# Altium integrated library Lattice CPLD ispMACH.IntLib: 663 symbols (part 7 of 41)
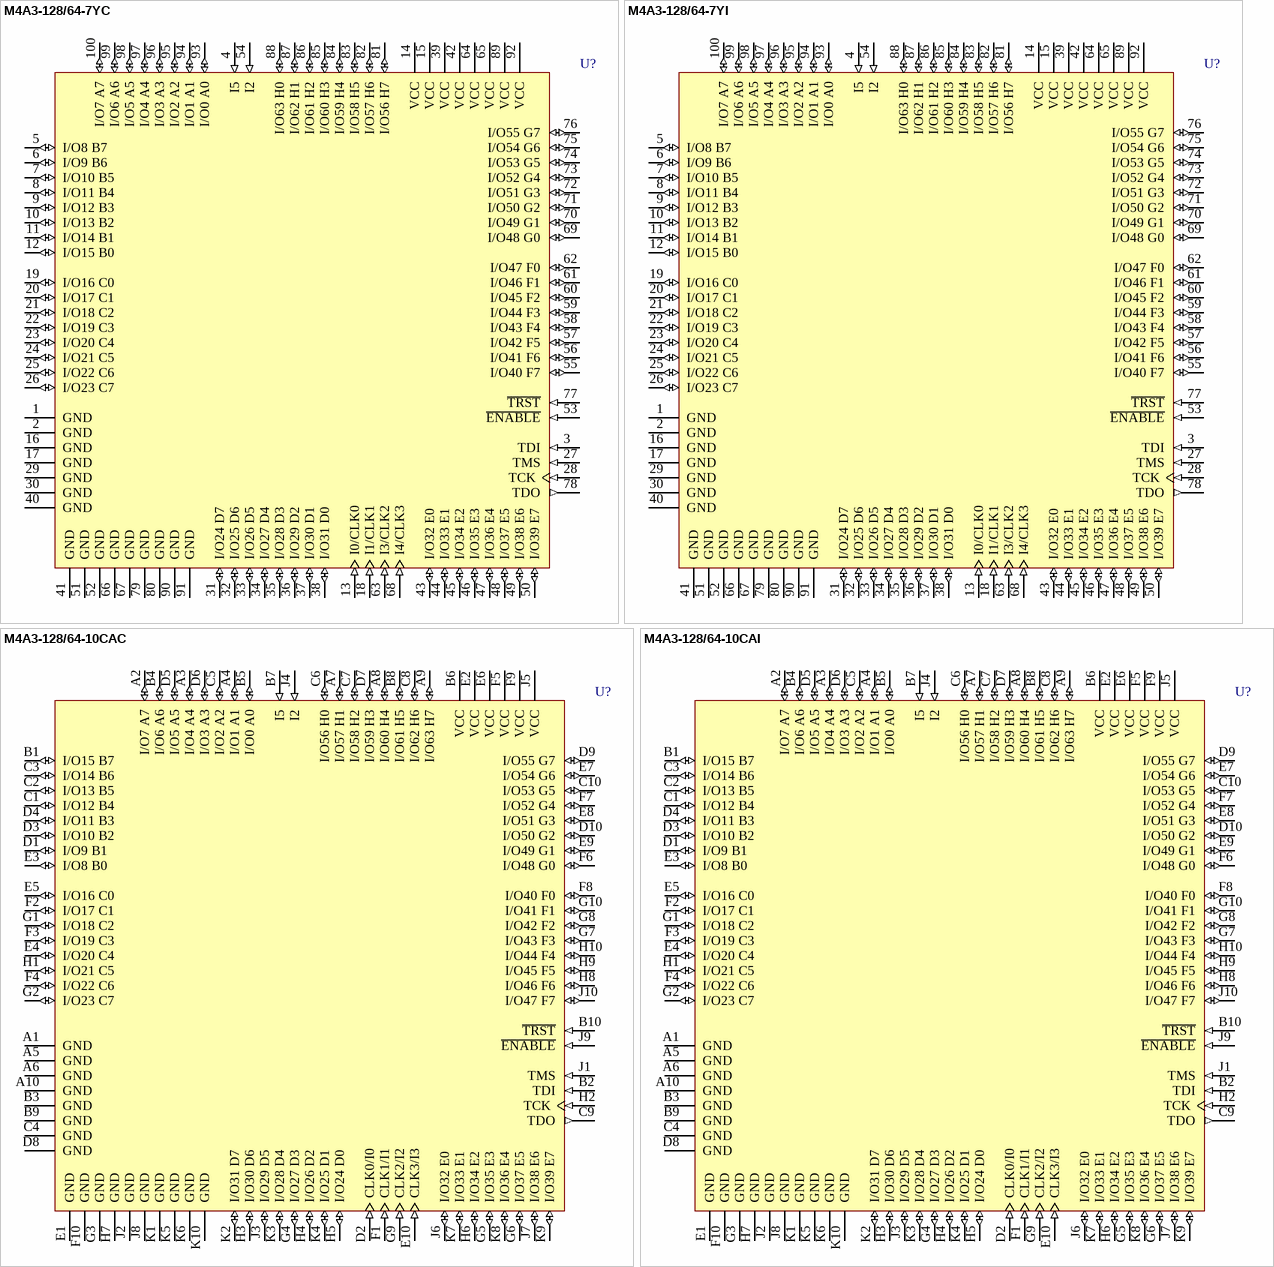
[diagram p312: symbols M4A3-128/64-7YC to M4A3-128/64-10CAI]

## M4A3-128/64-7YI
designator U?
High-Performance EE CMOS In-System Programmable Logic
footprint PQFP100_N (QFP, 100-Leads, Body 20x14mm, Pitch 0.65mm, IPC Medium Density)
footprint PQFP100_L (QFP, 100-Leads, Body 20x14mm, Pitch 0.65mm, IPC High Density)
footprint PQFP100_M (QFP, 100-Leads, Body 20x14mm, Pitch 0.65mm, IPC Low Density)
3D model PQFP-100 (100-Pin Quad Flat Pack Rectangular 0.65 mm Pitch)
pins: 1 GND (power), 2 GND (power), 3 TDI (in), 4 I5 (in), 5 I/O8 B7 (io), 6 I/O9 B6 (io), 7 I/O10 B5 (io), 8 I/O11 B4 (io), 9 I/O12 B3 (io), 10 I/O13 B2 (io), 11 I/O14 B1 (io), 12 I/O15 B0 (io), 13 I0/CLK0 (in), 14 VCC (power), 15 VCC (power), 16 GND (power), 17 GND (power), 18 I1/CLK1 (in), 19 I/O16 C0 (io), 20 I/O17 C1 (io), 21 I/O18 C2 (io), 22 I/O19 C3 (io), 23 I/O20 C4 (io), 24 I/O21 C5 (io), 25 I/O22 C6 (io), 26 I/O23 C7 (io), 27 TMS (in), 28 TCK (in), 29 GND (power), 30 GND (power), 31 I/O24 D7 (io), 32 I/O25 D6 (io), 33 I/O26 D5 (io), 34 I/O27 D4 (io), 35 I/O28 D3 (io), 36 I/O29 D2 (io), 37 I/O30 D1 (io), 38 I/O31 D0 (io), 39 VCC (power), 40 GND (power), 41 GND (power), 42 VCC (power), 43 I/O32 E0 (io), 44 I/O33 E1 (io), 45 I/O34 E2 (io), 46 I/O35 E3 (io), 47 I/O36 E4 (io), 48 I/O37 E5 (io), 49 I/O38 E6 (io), 50 I/O39 E7 (io), 51 GND (power), 52 GND (power), 53 ~{ENABLE} (in), 54 I2 (in), 55 I/O40 F7 (io), 56 I/O41 F6 (io), 57 I/O42 F5 (io), 58 I/O43 F4 (io), 59 I/O44 F3 (io), 60 I/O45 F2 (io), 61 I/O46 F1 (io), 62 I/O47 F0 (io), 63 I3/CLK2 (in), 64 VCC (power), 65 VCC (power), 66 GND (power), 67 GND (power), 68 I4/CLK3 (in), 69 I/O48 G0 (io), 70 I/O49 G1 (io), 71 I/O50 G2 (io), 72 I/O51 G3 (io), 73 I/O52 G4 (io), 74 I/O53 G5 (io), 75 I/O54 G6 (io), 76 I/O55 G7 (io), 77 ~{TRST} (in), 78 TDO (out), 79 GND (power), 80 GND (power), 81 I/O56 H7 (io), 82 I/O57 H6 (io), 83 I/O58 H5 (io), 84 I/O59 H4 (io), 85 I/O60 H3 (io), 86 I/O61 H2 (io), 87 I/O62 H1 (io), 88 I/O63 H0 (io), 89 VCC (power), 90 GND (power), 91 GND (power), 92 VCC (power), 93 I/O0 A0 (io), 94 I/O1 A1 (io), 95 I/O2 A2 (io), 96 I/O3 A3 (io), 97 I/O4 A4 (io), 98 I/O5 A5 (io), 99 I/O6 A6 (io), 100 I/O7 A7 (io)

## M4A3-128/64-10CAC
designator U?
High-Performance EE CMOS In-System Programmable Logic
footprint caBGA100 (BGA, 100-Leads, Body 10x10mm, Pitch 0.8mm)
3D model M4A3-CaBGA100 (100-Ball Chip Array Ball Grid Array (caBGA100))
pins: A1 GND (power), A2 I/O7 A7 (io), A3 I/O4 A4 (io), A4 I/O1 A1 (io), A5 GND (power), A6 GND (power), A7 I/O57 H1 (io), A8 I/O60 H4 (io), A9 I/O63 H7 (io), A10 GND (power), B1 I/O15 B7 (io), B2 TDI (in), B3 GND (power), B4 I/O6 A6 (io), B5 I/O0 A0 (io), B6 VCC (power), B7 I5 (in), B8 I/O61 H5 (io), B9 GND (power), B10 ~{TRST} (in), C1 I/O12 B4 (io), C2 I/O13 B5 (io), C3 I/O14 B6 (io), C4 GND (power), C5 I/O2 A2 (io), C6 I/O56 H0 (io), C7 I/O58 H2 (io), C8 I/O62 H6 (io), C9 TDO (out), C10 I/O53 G5 (io), D1 I/O9 B1 (io), D2 CLK0/I0 (in), D3 I/O10 B2 (io), D4 I/O11 B3 (io), D5 I/O5 A5 (io), D6 I/O3 A3 (io), D7 I/O59 H3 (io), D8 GND (power), D9 I/O55 G7 (io), D10 I/O50 G2 (io), E1 GND (power), E2 VCC (power), E3 I/O8 B0 (io), E4 I/O20 C4 (io), E5 I/O16 C0 (io), E6 VCC (power), E7 I/O54 G6 (io), E8 I/O51 G3 (io), E9 I/O49 G1 (io), E10 CLK3/I3 (in), F1 CLK1/I1 (in), F2 I/O17 C1 (io), F3 I/O19 C3 (io), F4 I/O22 C6 (io), F5 VCC (power), F6 I/O48 G0 (io), F7 I/O52 G4 (io), F8 I/O40 F0 (io), F9 VCC (power), F10 GND (power), G1 I/O18 C2 (io), G2 I/O23 C7 (io), G3 GND (power), G4 I/O27 D3 (io), G5 I/O35 E3 (io), G6 I/O37 E5 (io), G7 I/O43 F3 (io), G8 I/O42 F2 (io), G9 CLK2/I2 (in), G10 I/O41 F1 (io), H1 I/O21 C5 (io), H2 TCK (in), H3 I/O30 D6 (io), H4 I/O26 D2 (io), H5 I/O24 D0 (io), H6 I/O34 E2 (io), H7 GND (power), H8 I/O46 F6 (io), H9 I/O45 F5 (io), H10 I/O44 F4 (io), J1 TMS (in), J2 GND (power), J3 I/O29 D5 (io), J4 I2 (in), J5 VCC (power), J6 I/O32 E0 (io), J7 I/O38 E6 (io), J8 GND (power), J9 ~{ENABLE} (in), J10 I/O47 F7 (io), K1 GND (power), K2 I/O31 D7 (io), K3 I/O28 D4 (io), K4 I/O25 D1 (io), K5 GND (power), K6 GND (power), K7 I/O33 E1 (io), K8 I/O36 E4 (io), K9 I/O39 E7 (io), K10 GND (power)

## M4A3-128/64-10CAI
designator U?
High-Performance EE CMOS In-System Programmable Logic
footprint caBGA100 (BGA, 100-Leads, Body 10x10mm, Pitch 0.8mm)
3D model M4A3-CaBGA100 (100-Ball Chip Array Ball Grid Array (caBGA100))
pins: A1 GND (power), A2 I/O7 A7 (io), A3 I/O4 A4 (io), A4 I/O1 A1 (io), A5 GND (power), A6 GND (power), A7 I/O57 H1 (io), A8 I/O60 H4 (io), A9 I/O63 H7 (io), A10 GND (power), B1 I/O15 B7 (io), B2 TDI (in), B3 GND (power), B4 I/O6 A6 (io), B5 I/O0 A0 (io), B6 VCC (power), B7 I5 (in), B8 I/O61 H5 (io), B9 GND (power), B10 ~{TRST} (in), C1 I/O12 B4 (io), C2 I/O13 B5 (io), C3 I/O14 B6 (io), C4 GND (power), C5 I/O2 A2 (io), C6 I/O56 H0 (io), C7 I/O58 H2 (io), C8 I/O62 H6 (io), C9 TDO (out), C10 I/O53 G5 (io), D1 I/O9 B1 (io), D2 CLK0/I0 (in), D3 I/O10 B2 (io), D4 I/O11 B3 (io), D5 I/O5 A5 (io), D6 I/O3 A3 (io), D7 I/O59 H3 (io), D8 GND (power), D9 I/O55 G7 (io), D10 I/O50 G2 (io), E1 GND (power), E2 VCC (power), E3 I/O8 B0 (io), E4 I/O20 C4 (io), E5 I/O16 C0 (io), E6 VCC (power), E7 I/O54 G6 (io), E8 I/O51 G3 (io), E9 I/O49 G1 (io), E10 CLK3/I3 (in), F1 CLK1/I1 (in), F2 I/O17 C1 (io), F3 I/O19 C3 (io), F4 I/O22 C6 (io), F5 VCC (power), F6 I/O48 G0 (io), F7 I/O52 G4 (io), F8 I/O40 F0 (io), F9 VCC (power), F10 GND (power), G1 I/O18 C2 (io), G2 I/O23 C7 (io), G3 GND (power), G4 I/O27 D3 (io), G5 I/O35 E3 (io), G6 I/O37 E5 (io), G7 I/O43 F3 (io), G8 I/O42 F2 (io), G9 CLK2/I2 (in), G10 I/O41 F1 (io), H1 I/O21 C5 (io), H2 TCK (in), H3 I/O30 D6 (io), H4 I/O26 D2 (io), H5 I/O24 D0 (io), H6 I/O34 E2 (io), H7 GND (power), H8 I/O46 F6 (io), H9 I/O45 F5 (io), H10 I/O44 F4 (io), J1 TMS (in), J2 GND (power), J3 I/O29 D5 (io), J4 I2 (in), J5 VCC (power), J6 I/O32 E0 (io), J7 I/O38 E6 (io), J8 GND (power), J9 ~{ENABLE} (in), J10 I/O47 F7 (io), K1 GND (power), K2 I/O31 D7 (io), K3 I/O28 D4 (io), K4 I/O25 D1 (io), K5 GND (power), K6 GND (power), K7 I/O33 E1 (io), K8 I/O36 E4 (io), K9 I/O39 E7 (io), K10 GND (power)

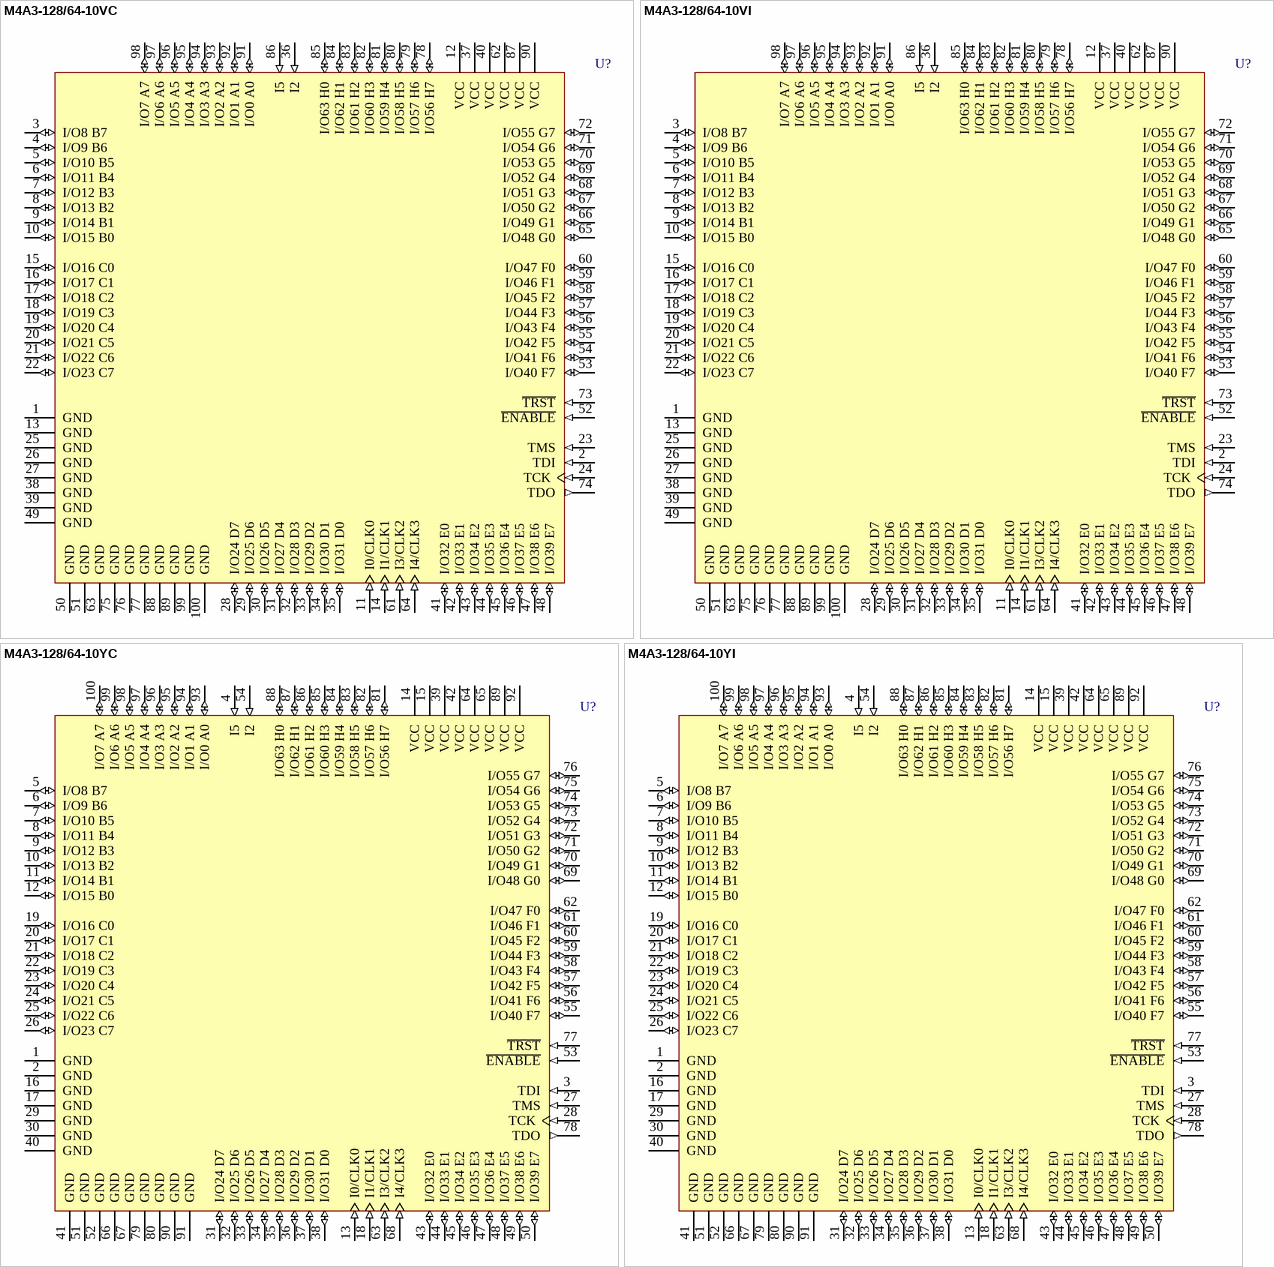
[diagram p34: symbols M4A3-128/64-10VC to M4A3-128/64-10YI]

## M4A3-128/64-10VC
designator U?
High-Performance EE CMOS In-System Programmable Logic
footprint TQFP100_N (Thin QFP, 100-Leads, Body 14x14mm, Pitch 0.5mm, IPC Medium Density)
footprint TQFP100_L (Thin QFP, 100-Leads, Body 14x14mm, Pitch 0.5mm, IPC High Density)
footprint TQFP100_M (Thin QFP, 100-Leads, Body 14x14mm, Pitch 0.5mm, IPC Low Density)
3D model M4A3-TQFP100 (100-Pin Thin Quad Flat Pack (TQFP100))
pins: 1 GND (power), 2 TDI (in), 3 I/O8 B7 (io), 4 I/O9 B6 (io), 5 I/O10 B5 (io), 6 I/O11 B4 (io), 7 I/O12 B3 (io), 8 I/O13 B2 (io), 9 I/O14 B1 (io), 10 I/O15 B0 (io), 11 I0/CLK0 (in), 12 VCC (power), 13 GND (power), 14 I1/CLK1 (in), 15 I/O16 C0 (io), 16 I/O17 C1 (io), 17 I/O18 C2 (io), 18 I/O19 C3 (io), 19 I/O20 C4 (io), 20 I/O21 C5 (io), 21 I/O22 C6 (io), 22 I/O23 C7 (io), 23 TMS (in), 24 TCK (in), 25 GND (power), 26 GND (power), 27 GND (power), 28 I/O24 D7 (io), 29 I/O25 D6 (io), 30 I/O26 D5 (io), 31 I/O27 D4 (io), 32 I/O28 D3 (io), 33 I/O29 D2 (io), 34 I/O30 D1 (io), 35 I/O31 D0 (io), 36 I2 (in), 37 VCC (power), 38 GND (power), 39 GND (power), 40 VCC (power), 41 I/O32 E0 (io), 42 I/O33 E1 (io), 43 I/O34 E2 (io), 44 I/O35 E3 (io), 45 I/O36 E4 (io), 46 I/O37 E5 (io), 47 I/O38 E6 (io), 48 I/O39 E7 (io), 49 GND (power), 50 GND (power), 51 GND (power), 52 ~{ENABLE} (in), 53 I/O40 F7 (io), 54 I/O41 F6 (io), 55 I/O42 F5 (io), 56 I/O43 F4 (io), 57 I/O44 F3 (io), 58 I/O45 F2 (io), 59 I/O46 F1 (io), 60 I/O47 F0 (io), 61 I3/CLK2 (in), 62 VCC (power), 63 GND (power), 64 I4/CLK3 (in), 65 I/O48 G0 (io), 66 I/O49 G1 (io), 67 I/O50 G2 (io), 68 I/O51 G3 (io), 69 I/O52 G4 (io), 70 I/O53 G5 (io), 71 I/O54 G6 (io), 72 I/O55 G7 (io), 73 ~{TRST} (in), 74 TDO (out), 75 GND (power), 76 GND (power), 77 GND (power), 78 I/O56 H7 (io), 79 I/O57 H6 (io), 80 I/O58 H5 (io), 81 I/O59 H4 (io), 82 I/O60 H3 (io), 83 I/O61 H2 (io), 84 I/O62 H1 (io), 85 I/O63 H0 (io), 86 I5 (in), 87 VCC (power), 88 GND (power), 89 GND (power), 90 VCC (power), 91 I/O0 A0 (io), 92 I/O1 A1 (io), 93 I/O2 A2 (io), 94 I/O3 A3 (io), 95 I/O4 A4 (io), 96 I/O5 A5 (io), 97 I/O6 A6 (io), 98 I/O7 A7 (io), 99 GND (power), 100 GND (power)

## M4A3-128/64-10VI
designator U?
High-Performance EE CMOS In-System Programmable Logic
footprint TQFP100_N (Thin QFP, 100-Leads, Body 14x14mm, Pitch 0.5mm, IPC Medium Density)
footprint TQFP100_L (Thin QFP, 100-Leads, Body 14x14mm, Pitch 0.5mm, IPC High Density)
footprint TQFP100_M (Thin QFP, 100-Leads, Body 14x14mm, Pitch 0.5mm, IPC Low Density)
3D model M4A3-TQFP100 (100-Pin Thin Quad Flat Pack (TQFP100))
pins: 1 GND (power), 2 TDI (in), 3 I/O8 B7 (io), 4 I/O9 B6 (io), 5 I/O10 B5 (io), 6 I/O11 B4 (io), 7 I/O12 B3 (io), 8 I/O13 B2 (io), 9 I/O14 B1 (io), 10 I/O15 B0 (io), 11 I0/CLK0 (in), 12 VCC (power), 13 GND (power), 14 I1/CLK1 (in), 15 I/O16 C0 (io), 16 I/O17 C1 (io), 17 I/O18 C2 (io), 18 I/O19 C3 (io), 19 I/O20 C4 (io), 20 I/O21 C5 (io), 21 I/O22 C6 (io), 22 I/O23 C7 (io), 23 TMS (in), 24 TCK (in), 25 GND (power), 26 GND (power), 27 GND (power), 28 I/O24 D7 (io), 29 I/O25 D6 (io), 30 I/O26 D5 (io), 31 I/O27 D4 (io), 32 I/O28 D3 (io), 33 I/O29 D2 (io), 34 I/O30 D1 (io), 35 I/O31 D0 (io), 36 I2 (in), 37 VCC (power), 38 GND (power), 39 GND (power), 40 VCC (power), 41 I/O32 E0 (io), 42 I/O33 E1 (io), 43 I/O34 E2 (io), 44 I/O35 E3 (io), 45 I/O36 E4 (io), 46 I/O37 E5 (io), 47 I/O38 E6 (io), 48 I/O39 E7 (io), 49 GND (power), 50 GND (power), 51 GND (power), 52 ~{ENABLE} (in), 53 I/O40 F7 (io), 54 I/O41 F6 (io), 55 I/O42 F5 (io), 56 I/O43 F4 (io), 57 I/O44 F3 (io), 58 I/O45 F2 (io), 59 I/O46 F1 (io), 60 I/O47 F0 (io), 61 I3/CLK2 (in), 62 VCC (power), 63 GND (power), 64 I4/CLK3 (in), 65 I/O48 G0 (io), 66 I/O49 G1 (io), 67 I/O50 G2 (io), 68 I/O51 G3 (io), 69 I/O52 G4 (io), 70 I/O53 G5 (io), 71 I/O54 G6 (io), 72 I/O55 G7 (io), 73 ~{TRST} (in), 74 TDO (out), 75 GND (power), 76 GND (power), 77 GND (power), 78 I/O56 H7 (io), 79 I/O57 H6 (io), 80 I/O58 H5 (io), 81 I/O59 H4 (io), 82 I/O60 H3 (io), 83 I/O61 H2 (io), 84 I/O62 H1 (io), 85 I/O63 H0 (io), 86 I5 (in), 87 VCC (power), 88 GND (power), 89 GND (power), 90 VCC (power), 91 I/O0 A0 (io), 92 I/O1 A1 (io), 93 I/O2 A2 (io), 94 I/O3 A3 (io), 95 I/O4 A4 (io), 96 I/O5 A5 (io), 97 I/O6 A6 (io), 98 I/O7 A7 (io), 99 GND (power), 100 GND (power)

## M4A3-128/64-10YC
designator U?
High-Performance EE CMOS In-System Programmable Logic
footprint PQFP100_N (QFP, 100-Leads, Body 20x14mm, Pitch 0.65mm, IPC Medium Density)
footprint PQFP100_L (QFP, 100-Leads, Body 20x14mm, Pitch 0.65mm, IPC High Density)
footprint PQFP100_M (QFP, 100-Leads, Body 20x14mm, Pitch 0.65mm, IPC Low Density)
3D model PQFP-100 (100-Pin Quad Flat Pack Rectangular 0.65 mm Pitch)
pins: 1 GND (power), 2 GND (power), 3 TDI (in), 4 I5 (in), 5 I/O8 B7 (io), 6 I/O9 B6 (io), 7 I/O10 B5 (io), 8 I/O11 B4 (io), 9 I/O12 B3 (io), 10 I/O13 B2 (io), 11 I/O14 B1 (io), 12 I/O15 B0 (io), 13 I0/CLK0 (in), 14 VCC (power), 15 VCC (power), 16 GND (power), 17 GND (power), 18 I1/CLK1 (in), 19 I/O16 C0 (io), 20 I/O17 C1 (io), 21 I/O18 C2 (io), 22 I/O19 C3 (io), 23 I/O20 C4 (io), 24 I/O21 C5 (io), 25 I/O22 C6 (io), 26 I/O23 C7 (io), 27 TMS (in), 28 TCK (in), 29 GND (power), 30 GND (power), 31 I/O24 D7 (io), 32 I/O25 D6 (io), 33 I/O26 D5 (io), 34 I/O27 D4 (io), 35 I/O28 D3 (io), 36 I/O29 D2 (io), 37 I/O30 D1 (io), 38 I/O31 D0 (io), 39 VCC (power), 40 GND (power), 41 GND (power), 42 VCC (power), 43 I/O32 E0 (io), 44 I/O33 E1 (io), 45 I/O34 E2 (io), 46 I/O35 E3 (io), 47 I/O36 E4 (io), 48 I/O37 E5 (io), 49 I/O38 E6 (io), 50 I/O39 E7 (io), 51 GND (power), 52 GND (power), 53 ~{ENABLE} (in), 54 I2 (in), 55 I/O40 F7 (io), 56 I/O41 F6 (io), 57 I/O42 F5 (io), 58 I/O43 F4 (io), 59 I/O44 F3 (io), 60 I/O45 F2 (io), 61 I/O46 F1 (io), 62 I/O47 F0 (io), 63 I3/CLK2 (in), 64 VCC (power), 65 VCC (power), 66 GND (power), 67 GND (power), 68 I4/CLK3 (in), 69 I/O48 G0 (io), 70 I/O49 G1 (io), 71 I/O50 G2 (io), 72 I/O51 G3 (io), 73 I/O52 G4 (io), 74 I/O53 G5 (io), 75 I/O54 G6 (io), 76 I/O55 G7 (io), 77 ~{TRST} (in), 78 TDO (out), 79 GND (power), 80 GND (power), 81 I/O56 H7 (io), 82 I/O57 H6 (io), 83 I/O58 H5 (io), 84 I/O59 H4 (io), 85 I/O60 H3 (io), 86 I/O61 H2 (io), 87 I/O62 H1 (io), 88 I/O63 H0 (io), 89 VCC (power), 90 GND (power), 91 GND (power), 92 VCC (power), 93 I/O0 A0 (io), 94 I/O1 A1 (io), 95 I/O2 A2 (io), 96 I/O3 A3 (io), 97 I/O4 A4 (io), 98 I/O5 A5 (io), 99 I/O6 A6 (io), 100 I/O7 A7 (io)

## M4A3-128/64-10YI
designator U?
High-Performance EE CMOS In-System Programmable Logic
footprint PQFP100_N (QFP, 100-Leads, Body 20x14mm, Pitch 0.65mm, IPC Medium Density)
footprint PQFP100_L (QFP, 100-Leads, Body 20x14mm, Pitch 0.65mm, IPC High Density)
footprint PQFP100_M (QFP, 100-Leads, Body 20x14mm, Pitch 0.65mm, IPC Low Density)
3D model PQFP-100 (100-Pin Quad Flat Pack Rectangular 0.65 mm Pitch)
pins: 1 GND (power), 2 GND (power), 3 TDI (in), 4 I5 (in), 5 I/O8 B7 (io), 6 I/O9 B6 (io), 7 I/O10 B5 (io), 8 I/O11 B4 (io), 9 I/O12 B3 (io), 10 I/O13 B2 (io), 11 I/O14 B1 (io), 12 I/O15 B0 (io), 13 I0/CLK0 (in), 14 VCC (power), 15 VCC (power), 16 GND (power), 17 GND (power), 18 I1/CLK1 (in), 19 I/O16 C0 (io), 20 I/O17 C1 (io), 21 I/O18 C2 (io), 22 I/O19 C3 (io), 23 I/O20 C4 (io), 24 I/O21 C5 (io), 25 I/O22 C6 (io), 26 I/O23 C7 (io), 27 TMS (in), 28 TCK (in), 29 GND (power), 30 GND (power), 31 I/O24 D7 (io), 32 I/O25 D6 (io), 33 I/O26 D5 (io), 34 I/O27 D4 (io), 35 I/O28 D3 (io), 36 I/O29 D2 (io), 37 I/O30 D1 (io), 38 I/O31 D0 (io), 39 VCC (power), 40 GND (power), 41 GND (power), 42 VCC (power), 43 I/O32 E0 (io), 44 I/O33 E1 (io), 45 I/O34 E2 (io), 46 I/O35 E3 (io), 47 I/O36 E4 (io), 48 I/O37 E5 (io), 49 I/O38 E6 (io), 50 I/O39 E7 (io), 51 GND (power), 52 GND (power), 53 ~{ENABLE} (in), 54 I2 (in), 55 I/O40 F7 (io), 56 I/O41 F6 (io), 57 I/O42 F5 (io), 58 I/O43 F4 (io), 59 I/O44 F3 (io), 60 I/O45 F2 (io), 61 I/O46 F1 (io), 62 I/O47 F0 (io), 63 I3/CLK2 (in), 64 VCC (power), 65 VCC (power), 66 GND (power), 67 GND (power), 68 I4/CLK3 (in), 69 I/O48 G0 (io), 70 I/O49 G1 (io), 71 I/O50 G2 (io), 72 I/O51 G3 (io), 73 I/O52 G4 (io), 74 I/O53 G5 (io), 75 I/O54 G6 (io), 76 I/O55 G7 (io), 77 ~{TRST} (in), 78 TDO (out), 79 GND (power), 80 GND (power), 81 I/O56 H7 (io), 82 I/O57 H6 (io), 83 I/O58 H5 (io), 84 I/O59 H4 (io), 85 I/O60 H3 (io), 86 I/O61 H2 (io), 87 I/O62 H1 (io), 88 I/O63 H0 (io), 89 VCC (power), 90 GND (power), 91 GND (power), 92 VCC (power), 93 I/O0 A0 (io), 94 I/O1 A1 (io), 95 I/O2 A2 (io), 96 I/O3 A3 (io), 97 I/O4 A4 (io), 98 I/O5 A5 (io), 99 I/O6 A6 (io), 100 I/O7 A7 (io)

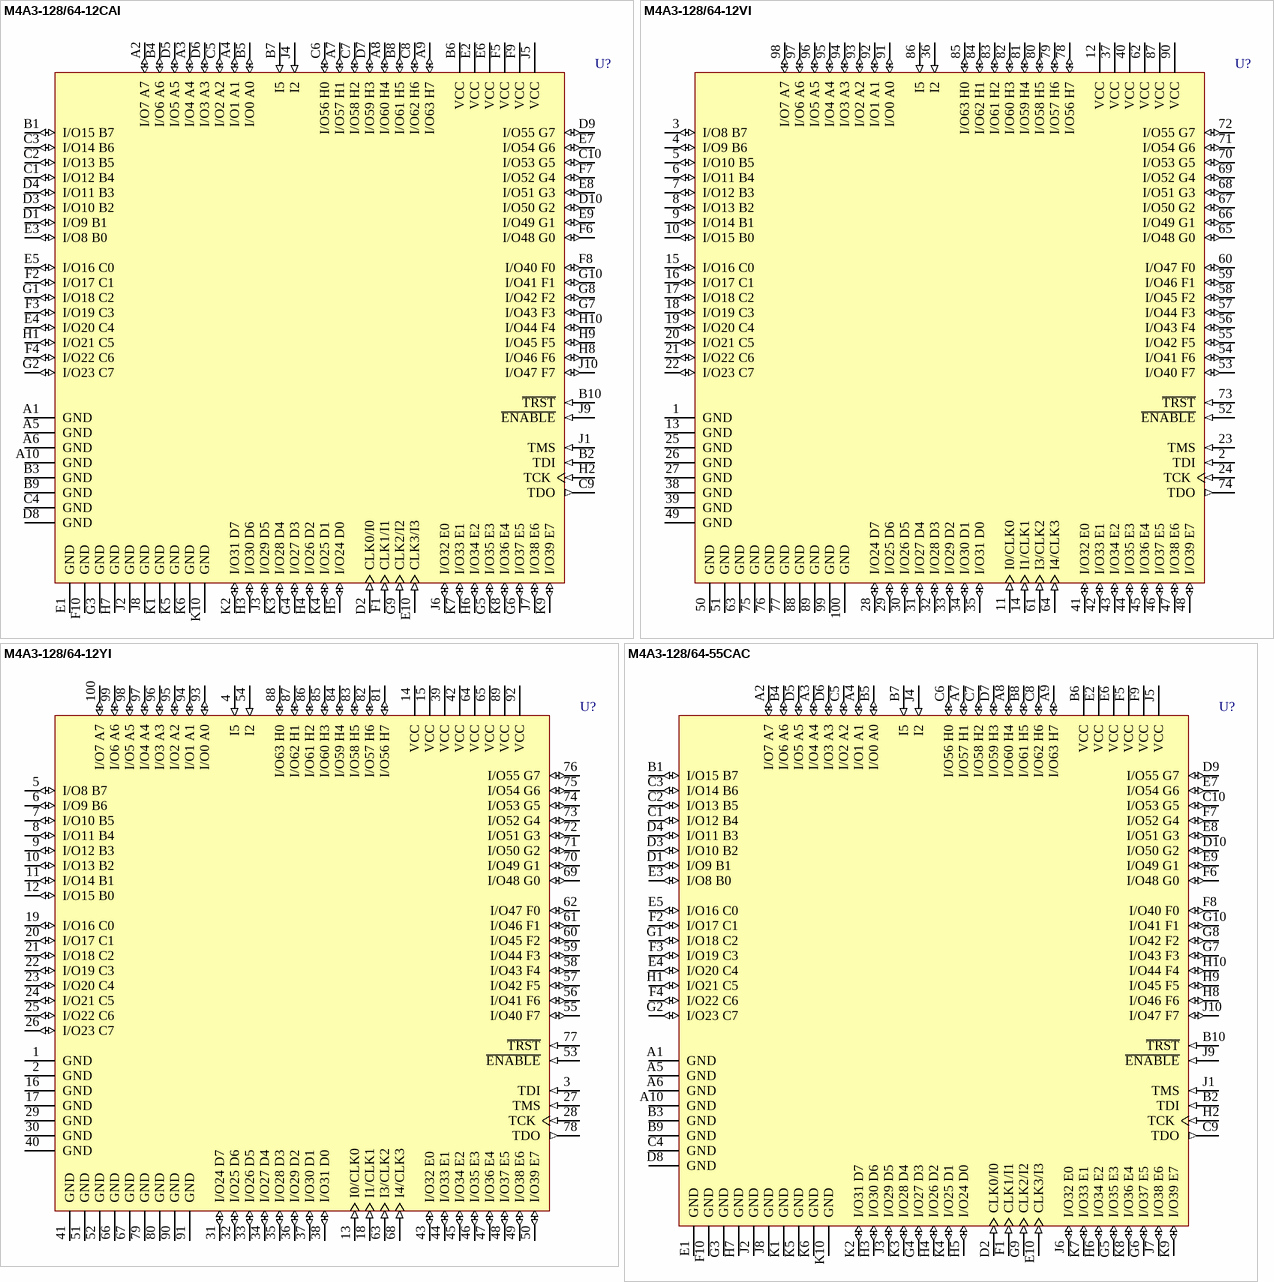
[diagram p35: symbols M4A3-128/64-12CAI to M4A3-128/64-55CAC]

## M4A3-128/64-12CAI
designator U?
High-Performance EE CMOS In-System Programmable Logic
footprint caBGA100 (BGA, 100-Leads, Body 10x10mm, Pitch 0.8mm)
3D model M4A3-CaBGA100 (100-Ball Chip Array Ball Grid Array (caBGA100))
pins: A1 GND (power), A2 I/O7 A7 (io), A3 I/O4 A4 (io), A4 I/O1 A1 (io), A5 GND (power), A6 GND (power), A7 I/O57 H1 (io), A8 I/O60 H4 (io), A9 I/O63 H7 (io), A10 GND (power), B1 I/O15 B7 (io), B2 TDI (in), B3 GND (power), B4 I/O6 A6 (io), B5 I/O0 A0 (io), B6 VCC (power), B7 I5 (in), B8 I/O61 H5 (io), B9 GND (power), B10 ~{TRST} (in), C1 I/O12 B4 (io), C2 I/O13 B5 (io), C3 I/O14 B6 (io), C4 GND (power), C5 I/O2 A2 (io), C6 I/O56 H0 (io), C7 I/O58 H2 (io), C8 I/O62 H6 (io), C9 TDO (out), C10 I/O53 G5 (io), D1 I/O9 B1 (io), D2 CLK0/I0 (in), D3 I/O10 B2 (io), D4 I/O11 B3 (io), D5 I/O5 A5 (io), D6 I/O3 A3 (io), D7 I/O59 H3 (io), D8 GND (power), D9 I/O55 G7 (io), D10 I/O50 G2 (io), E1 GND (power), E2 VCC (power), E3 I/O8 B0 (io), E4 I/O20 C4 (io), E5 I/O16 C0 (io), E6 VCC (power), E7 I/O54 G6 (io), E8 I/O51 G3 (io), E9 I/O49 G1 (io), E10 CLK3/I3 (in), F1 CLK1/I1 (in), F2 I/O17 C1 (io), F3 I/O19 C3 (io), F4 I/O22 C6 (io), F5 VCC (power), F6 I/O48 G0 (io), F7 I/O52 G4 (io), F8 I/O40 F0 (io), F9 VCC (power), F10 GND (power), G1 I/O18 C2 (io), G2 I/O23 C7 (io), G3 GND (power), G4 I/O27 D3 (io), G5 I/O35 E3 (io), G6 I/O37 E5 (io), G7 I/O43 F3 (io), G8 I/O42 F2 (io), G9 CLK2/I2 (in), G10 I/O41 F1 (io), H1 I/O21 C5 (io), H2 TCK (in), H3 I/O30 D6 (io), H4 I/O26 D2 (io), H5 I/O24 D0 (io), H6 I/O34 E2 (io), H7 GND (power), H8 I/O46 F6 (io), H9 I/O45 F5 (io), H10 I/O44 F4 (io), J1 TMS (in), J2 GND (power), J3 I/O29 D5 (io), J4 I2 (in), J5 VCC (power), J6 I/O32 E0 (io), J7 I/O38 E6 (io), J8 GND (power), J9 ~{ENABLE} (in), J10 I/O47 F7 (io), K1 GND (power), K2 I/O31 D7 (io), K3 I/O28 D4 (io), K4 I/O25 D1 (io), K5 GND (power), K6 GND (power), K7 I/O33 E1 (io), K8 I/O36 E4 (io), K9 I/O39 E7 (io), K10 GND (power)

## M4A3-128/64-12VI
designator U?
High-Performance EE CMOS In-System Programmable Logic
footprint TQFP100_N (Thin QFP, 100-Leads, Body 14x14mm, Pitch 0.5mm, IPC Medium Density)
footprint TQFP100_L (Thin QFP, 100-Leads, Body 14x14mm, Pitch 0.5mm, IPC High Density)
footprint TQFP100_M (Thin QFP, 100-Leads, Body 14x14mm, Pitch 0.5mm, IPC Low Density)
3D model M4A3-TQFP100 (100-Pin Thin Quad Flat Pack (TQFP100))
pins: 1 GND (power), 2 TDI (in), 3 I/O8 B7 (io), 4 I/O9 B6 (io), 5 I/O10 B5 (io), 6 I/O11 B4 (io), 7 I/O12 B3 (io), 8 I/O13 B2 (io), 9 I/O14 B1 (io), 10 I/O15 B0 (io), 11 I0/CLK0 (in), 12 VCC (power), 13 GND (power), 14 I1/CLK1 (in), 15 I/O16 C0 (io), 16 I/O17 C1 (io), 17 I/O18 C2 (io), 18 I/O19 C3 (io), 19 I/O20 C4 (io), 20 I/O21 C5 (io), 21 I/O22 C6 (io), 22 I/O23 C7 (io), 23 TMS (in), 24 TCK (in), 25 GND (power), 26 GND (power), 27 GND (power), 28 I/O24 D7 (io), 29 I/O25 D6 (io), 30 I/O26 D5 (io), 31 I/O27 D4 (io), 32 I/O28 D3 (io), 33 I/O29 D2 (io), 34 I/O30 D1 (io), 35 I/O31 D0 (io), 36 I2 (in), 37 VCC (power), 38 GND (power), 39 GND (power), 40 VCC (power), 41 I/O32 E0 (io), 42 I/O33 E1 (io), 43 I/O34 E2 (io), 44 I/O35 E3 (io), 45 I/O36 E4 (io), 46 I/O37 E5 (io), 47 I/O38 E6 (io), 48 I/O39 E7 (io), 49 GND (power), 50 GND (power), 51 GND (power), 52 ~{ENABLE} (in), 53 I/O40 F7 (io), 54 I/O41 F6 (io), 55 I/O42 F5 (io), 56 I/O43 F4 (io), 57 I/O44 F3 (io), 58 I/O45 F2 (io), 59 I/O46 F1 (io), 60 I/O47 F0 (io), 61 I3/CLK2 (in), 62 VCC (power), 63 GND (power), 64 I4/CLK3 (in), 65 I/O48 G0 (io), 66 I/O49 G1 (io), 67 I/O50 G2 (io), 68 I/O51 G3 (io), 69 I/O52 G4 (io), 70 I/O53 G5 (io), 71 I/O54 G6 (io), 72 I/O55 G7 (io), 73 ~{TRST} (in), 74 TDO (out), 75 GND (power), 76 GND (power), 77 GND (power), 78 I/O56 H7 (io), 79 I/O57 H6 (io), 80 I/O58 H5 (io), 81 I/O59 H4 (io), 82 I/O60 H3 (io), 83 I/O61 H2 (io), 84 I/O62 H1 (io), 85 I/O63 H0 (io), 86 I5 (in), 87 VCC (power), 88 GND (power), 89 GND (power), 90 VCC (power), 91 I/O0 A0 (io), 92 I/O1 A1 (io), 93 I/O2 A2 (io), 94 I/O3 A3 (io), 95 I/O4 A4 (io), 96 I/O5 A5 (io), 97 I/O6 A6 (io), 98 I/O7 A7 (io), 99 GND (power), 100 GND (power)

## M4A3-128/64-12YI
designator U?
High-Performance EE CMOS In-System Programmable Logic
footprint PQFP100_N (QFP, 100-Leads, Body 20x14mm, Pitch 0.65mm, IPC Medium Density)
footprint PQFP100_L (QFP, 100-Leads, Body 20x14mm, Pitch 0.65mm, IPC High Density)
footprint PQFP100_M (QFP, 100-Leads, Body 20x14mm, Pitch 0.65mm, IPC Low Density)
3D model PQFP-100 (100-Pin Quad Flat Pack Rectangular 0.65 mm Pitch)
pins: 1 GND (power), 2 GND (power), 3 TDI (in), 4 I5 (in), 5 I/O8 B7 (io), 6 I/O9 B6 (io), 7 I/O10 B5 (io), 8 I/O11 B4 (io), 9 I/O12 B3 (io), 10 I/O13 B2 (io), 11 I/O14 B1 (io), 12 I/O15 B0 (io), 13 I0/CLK0 (in), 14 VCC (power), 15 VCC (power), 16 GND (power), 17 GND (power), 18 I1/CLK1 (in), 19 I/O16 C0 (io), 20 I/O17 C1 (io), 21 I/O18 C2 (io), 22 I/O19 C3 (io), 23 I/O20 C4 (io), 24 I/O21 C5 (io), 25 I/O22 C6 (io), 26 I/O23 C7 (io), 27 TMS (in), 28 TCK (in), 29 GND (power), 30 GND (power), 31 I/O24 D7 (io), 32 I/O25 D6 (io), 33 I/O26 D5 (io), 34 I/O27 D4 (io), 35 I/O28 D3 (io), 36 I/O29 D2 (io), 37 I/O30 D1 (io), 38 I/O31 D0 (io), 39 VCC (power), 40 GND (power), 41 GND (power), 42 VCC (power), 43 I/O32 E0 (io), 44 I/O33 E1 (io), 45 I/O34 E2 (io), 46 I/O35 E3 (io), 47 I/O36 E4 (io), 48 I/O37 E5 (io), 49 I/O38 E6 (io), 50 I/O39 E7 (io), 51 GND (power), 52 GND (power), 53 ~{ENABLE} (in), 54 I2 (in), 55 I/O40 F7 (io), 56 I/O41 F6 (io), 57 I/O42 F5 (io), 58 I/O43 F4 (io), 59 I/O44 F3 (io), 60 I/O45 F2 (io), 61 I/O46 F1 (io), 62 I/O47 F0 (io), 63 I3/CLK2 (in), 64 VCC (power), 65 VCC (power), 66 GND (power), 67 GND (power), 68 I4/CLK3 (in), 69 I/O48 G0 (io), 70 I/O49 G1 (io), 71 I/O50 G2 (io), 72 I/O51 G3 (io), 73 I/O52 G4 (io), 74 I/O53 G5 (io), 75 I/O54 G6 (io), 76 I/O55 G7 (io), 77 ~{TRST} (in), 78 TDO (out), 79 GND (power), 80 GND (power), 81 I/O56 H7 (io), 82 I/O57 H6 (io), 83 I/O58 H5 (io), 84 I/O59 H4 (io), 85 I/O60 H3 (io), 86 I/O61 H2 (io), 87 I/O62 H1 (io), 88 I/O63 H0 (io), 89 VCC (power), 90 GND (power), 91 GND (power), 92 VCC (power), 93 I/O0 A0 (io), 94 I/O1 A1 (io), 95 I/O2 A2 (io), 96 I/O3 A3 (io), 97 I/O4 A4 (io), 98 I/O5 A5 (io), 99 I/O6 A6 (io), 100 I/O7 A7 (io)

## M4A3-128/64-55CAC
designator U?
High-Performance EE CMOS In-System Programmable Logic
footprint caBGA100 (BGA, 100-Leads, Body 10x10mm, Pitch 0.8mm)
3D model M4A3-CaBGA100 (100-Ball Chip Array Ball Grid Array (caBGA100))
pins: A1 GND (power), A2 I/O7 A7 (io), A3 I/O4 A4 (io), A4 I/O1 A1 (io), A5 GND (power), A6 GND (power), A7 I/O57 H1 (io), A8 I/O60 H4 (io), A9 I/O63 H7 (io), A10 GND (power), B1 I/O15 B7 (io), B2 TDI (in), B3 GND (power), B4 I/O6 A6 (io), B5 I/O0 A0 (io), B6 VCC (power), B7 I5 (in), B8 I/O61 H5 (io), B9 GND (power), B10 ~{TRST} (in), C1 I/O12 B4 (io), C2 I/O13 B5 (io), C3 I/O14 B6 (io), C4 GND (power), C5 I/O2 A2 (io), C6 I/O56 H0 (io), C7 I/O58 H2 (io), C8 I/O62 H6 (io), C9 TDO (out), C10 I/O53 G5 (io), D1 I/O9 B1 (io), D2 CLK0/I0 (in), D3 I/O10 B2 (io), D4 I/O11 B3 (io), D5 I/O5 A5 (io), D6 I/O3 A3 (io), D7 I/O59 H3 (io), D8 GND (power), D9 I/O55 G7 (io), D10 I/O50 G2 (io), E1 GND (power), E2 VCC (power), E3 I/O8 B0 (io), E4 I/O20 C4 (io), E5 I/O16 C0 (io), E6 VCC (power), E7 I/O54 G6 (io), E8 I/O51 G3 (io), E9 I/O49 G1 (io), E10 CLK3/I3 (in), F1 CLK1/I1 (in), F2 I/O17 C1 (io), F3 I/O19 C3 (io), F4 I/O22 C6 (io), F5 VCC (power), F6 I/O48 G0 (io), F7 I/O52 G4 (io), F8 I/O40 F0 (io), F9 VCC (power), F10 GND (power), G1 I/O18 C2 (io), G2 I/O23 C7 (io), G3 GND (power), G4 I/O27 D3 (io), G5 I/O35 E3 (io), G6 I/O37 E5 (io), G7 I/O43 F3 (io), G8 I/O42 F2 (io), G9 CLK2/I2 (in), G10 I/O41 F1 (io), H1 I/O21 C5 (io), H2 TCK (in), H3 I/O30 D6 (io), H4 I/O26 D2 (io), H5 I/O24 D0 (io), H6 I/O34 E2 (io), H7 GND (power), H8 I/O46 F6 (io), H9 I/O45 F5 (io), H10 I/O44 F4 (io), J1 TMS (in), J2 GND (power), J3 I/O29 D5 (io), J4 I2 (in), J5 VCC (power), J6 I/O32 E0 (io), J7 I/O38 E6 (io), J8 GND (power), J9 ~{ENABLE} (in), J10 I/O47 F7 (io), K1 GND (power), K2 I/O31 D7 (io), K3 I/O28 D4 (io), K4 I/O25 D1 (io), K5 GND (power), K6 GND (power), K7 I/O33 E1 (io), K8 I/O36 E4 (io), K9 I/O39 E7 (io), K10 GND (power)

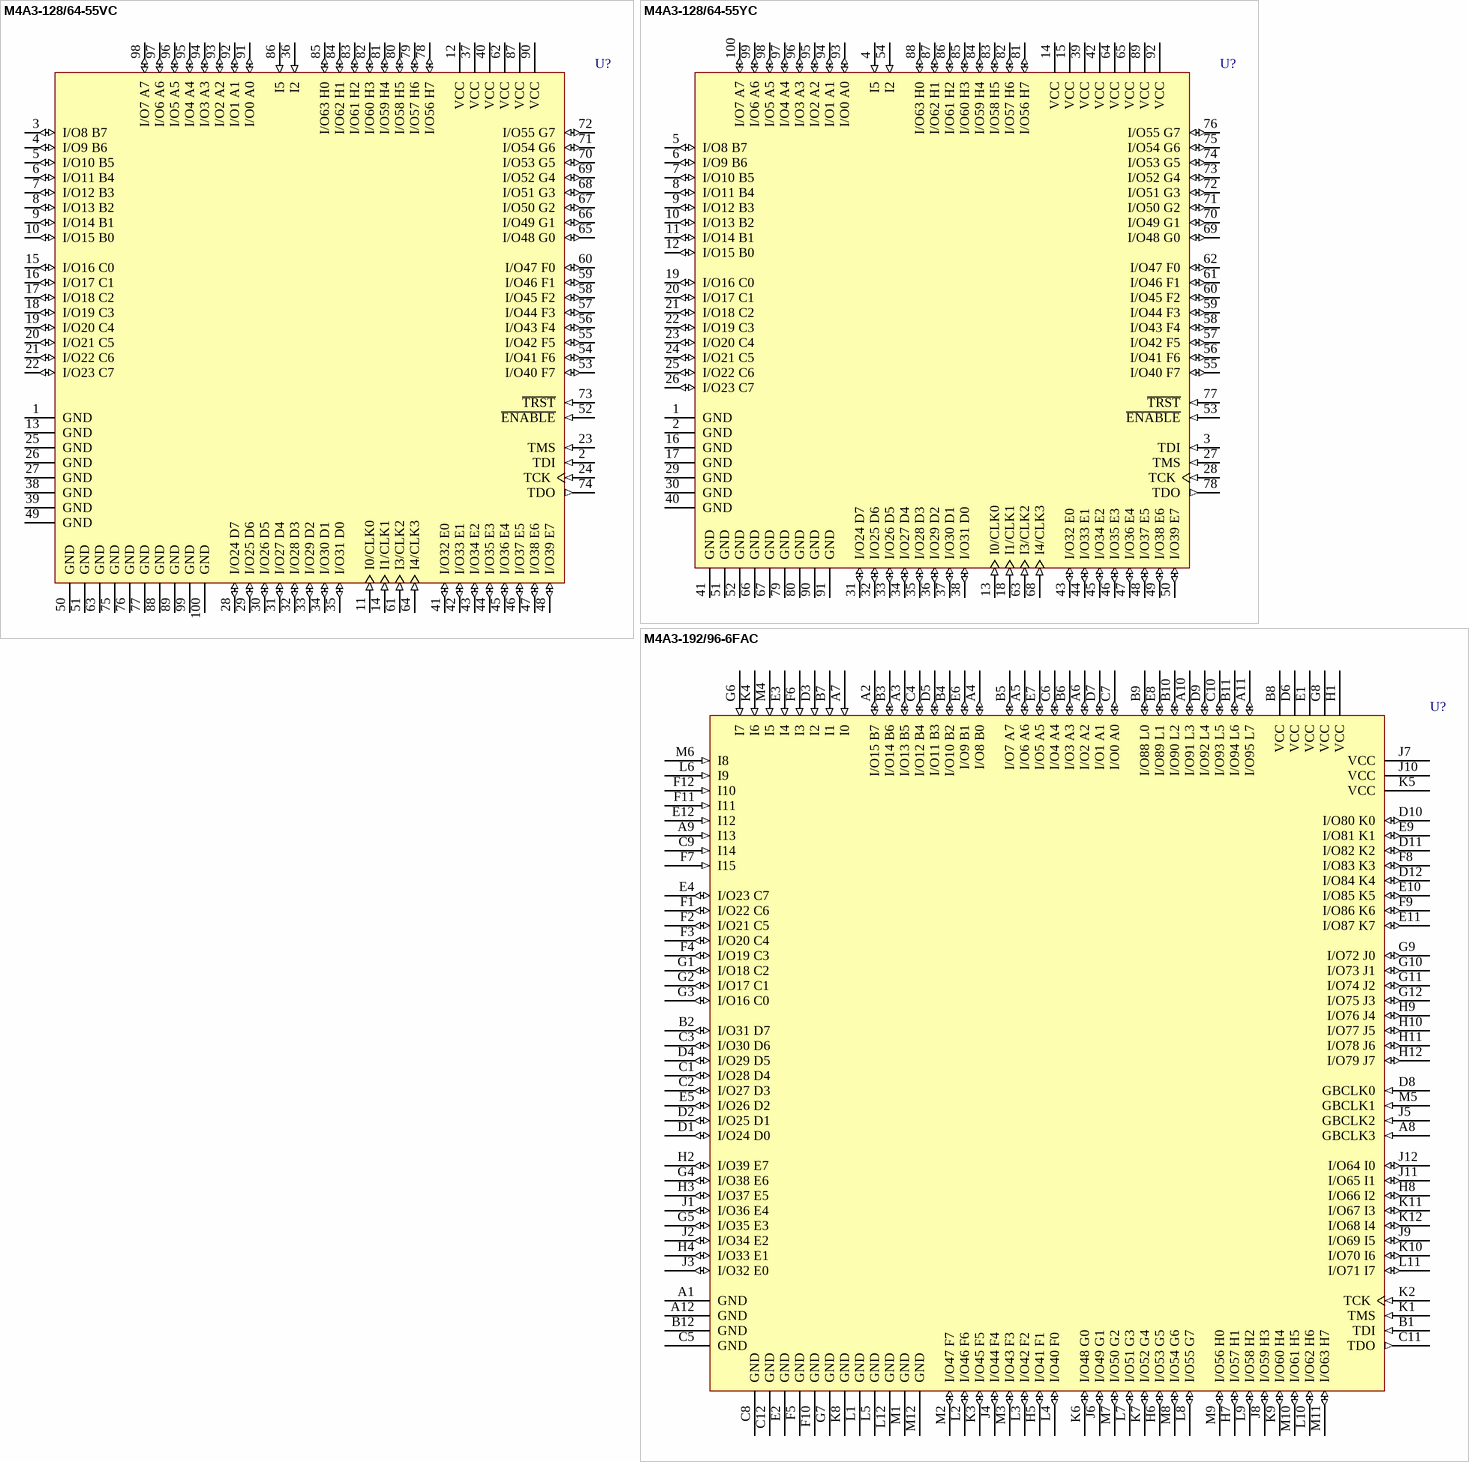
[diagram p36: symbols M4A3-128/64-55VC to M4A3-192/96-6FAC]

## M4A3-128/64-55VC
designator U?
High-Performance EE CMOS In-System Programmable Logic
footprint TQFP100_N (Thin QFP, 100-Leads, Body 14x14mm, Pitch 0.5mm, IPC Medium Density)
footprint TQFP100_L (Thin QFP, 100-Leads, Body 14x14mm, Pitch 0.5mm, IPC High Density)
footprint TQFP100_M (Thin QFP, 100-Leads, Body 14x14mm, Pitch 0.5mm, IPC Low Density)
3D model M4A3-TQFP100 (100-Pin Thin Quad Flat Pack (TQFP100))
pins: 1 GND (power), 2 TDI (in), 3 I/O8 B7 (io), 4 I/O9 B6 (io), 5 I/O10 B5 (io), 6 I/O11 B4 (io), 7 I/O12 B3 (io), 8 I/O13 B2 (io), 9 I/O14 B1 (io), 10 I/O15 B0 (io), 11 I0/CLK0 (in), 12 VCC (power), 13 GND (power), 14 I1/CLK1 (in), 15 I/O16 C0 (io), 16 I/O17 C1 (io), 17 I/O18 C2 (io), 18 I/O19 C3 (io), 19 I/O20 C4 (io), 20 I/O21 C5 (io), 21 I/O22 C6 (io), 22 I/O23 C7 (io), 23 TMS (in), 24 TCK (in), 25 GND (power), 26 GND (power), 27 GND (power), 28 I/O24 D7 (io), 29 I/O25 D6 (io), 30 I/O26 D5 (io), 31 I/O27 D4 (io), 32 I/O28 D3 (io), 33 I/O29 D2 (io), 34 I/O30 D1 (io), 35 I/O31 D0 (io), 36 I2 (in), 37 VCC (power), 38 GND (power), 39 GND (power), 40 VCC (power), 41 I/O32 E0 (io), 42 I/O33 E1 (io), 43 I/O34 E2 (io), 44 I/O35 E3 (io), 45 I/O36 E4 (io), 46 I/O37 E5 (io), 47 I/O38 E6 (io), 48 I/O39 E7 (io), 49 GND (power), 50 GND (power), 51 GND (power), 52 ~{ENABLE} (in), 53 I/O40 F7 (io), 54 I/O41 F6 (io), 55 I/O42 F5 (io), 56 I/O43 F4 (io), 57 I/O44 F3 (io), 58 I/O45 F2 (io), 59 I/O46 F1 (io), 60 I/O47 F0 (io), 61 I3/CLK2 (in), 62 VCC (power), 63 GND (power), 64 I4/CLK3 (in), 65 I/O48 G0 (io), 66 I/O49 G1 (io), 67 I/O50 G2 (io), 68 I/O51 G3 (io), 69 I/O52 G4 (io), 70 I/O53 G5 (io), 71 I/O54 G6 (io), 72 I/O55 G7 (io), 73 ~{TRST} (in), 74 TDO (out), 75 GND (power), 76 GND (power), 77 GND (power), 78 I/O56 H7 (io), 79 I/O57 H6 (io), 80 I/O58 H5 (io), 81 I/O59 H4 (io), 82 I/O60 H3 (io), 83 I/O61 H2 (io), 84 I/O62 H1 (io), 85 I/O63 H0 (io), 86 I5 (in), 87 VCC (power), 88 GND (power), 89 GND (power), 90 VCC (power), 91 I/O0 A0 (io), 92 I/O1 A1 (io), 93 I/O2 A2 (io), 94 I/O3 A3 (io), 95 I/O4 A4 (io), 96 I/O5 A5 (io), 97 I/O6 A6 (io), 98 I/O7 A7 (io), 99 GND (power), 100 GND (power)

## M4A3-128/64-55YC
designator U?
High-Performance EE CMOS In-System Programmable Logic
footprint PQFP100_N (QFP, 100-Leads, Body 20x14mm, Pitch 0.65mm, IPC Medium Density)
footprint PQFP100_L (QFP, 100-Leads, Body 20x14mm, Pitch 0.65mm, IPC High Density)
footprint PQFP100_M (QFP, 100-Leads, Body 20x14mm, Pitch 0.65mm, IPC Low Density)
3D model PQFP-100 (100-Pin Quad Flat Pack Rectangular 0.65 mm Pitch)
pins: 1 GND (power), 2 GND (power), 3 TDI (in), 4 I5 (in), 5 I/O8 B7 (io), 6 I/O9 B6 (io), 7 I/O10 B5 (io), 8 I/O11 B4 (io), 9 I/O12 B3 (io), 10 I/O13 B2 (io), 11 I/O14 B1 (io), 12 I/O15 B0 (io), 13 I0/CLK0 (in), 14 VCC (power), 15 VCC (power), 16 GND (power), 17 GND (power), 18 I1/CLK1 (in), 19 I/O16 C0 (io), 20 I/O17 C1 (io), 21 I/O18 C2 (io), 22 I/O19 C3 (io), 23 I/O20 C4 (io), 24 I/O21 C5 (io), 25 I/O22 C6 (io), 26 I/O23 C7 (io), 27 TMS (in), 28 TCK (in), 29 GND (power), 30 GND (power), 31 I/O24 D7 (io), 32 I/O25 D6 (io), 33 I/O26 D5 (io), 34 I/O27 D4 (io), 35 I/O28 D3 (io), 36 I/O29 D2 (io), 37 I/O30 D1 (io), 38 I/O31 D0 (io), 39 VCC (power), 40 GND (power), 41 GND (power), 42 VCC (power), 43 I/O32 E0 (io), 44 I/O33 E1 (io), 45 I/O34 E2 (io), 46 I/O35 E3 (io), 47 I/O36 E4 (io), 48 I/O37 E5 (io), 49 I/O38 E6 (io), 50 I/O39 E7 (io), 51 GND (power), 52 GND (power), 53 ~{ENABLE} (in), 54 I2 (in), 55 I/O40 F7 (io), 56 I/O41 F6 (io), 57 I/O42 F5 (io), 58 I/O43 F4 (io), 59 I/O44 F3 (io), 60 I/O45 F2 (io), 61 I/O46 F1 (io), 62 I/O47 F0 (io), 63 I3/CLK2 (in), 64 VCC (power), 65 VCC (power), 66 GND (power), 67 GND (power), 68 I4/CLK3 (in), 69 I/O48 G0 (io), 70 I/O49 G1 (io), 71 I/O50 G2 (io), 72 I/O51 G3 (io), 73 I/O52 G4 (io), 74 I/O53 G5 (io), 75 I/O54 G6 (io), 76 I/O55 G7 (io), 77 ~{TRST} (in), 78 TDO (out), 79 GND (power), 80 GND (power), 81 I/O56 H7 (io), 82 I/O57 H6 (io), 83 I/O58 H5 (io), 84 I/O59 H4 (io), 85 I/O60 H3 (io), 86 I/O61 H2 (io), 87 I/O62 H1 (io), 88 I/O63 H0 (io), 89 VCC (power), 90 GND (power), 91 GND (power), 92 VCC (power), 93 I/O0 A0 (io), 94 I/O1 A1 (io), 95 I/O2 A2 (io), 96 I/O3 A3 (io), 97 I/O4 A4 (io), 98 I/O5 A5 (io), 99 I/O6 A6 (io), 100 I/O7 A7 (io)

## M4A3-192/96-6FAC
designator U?
High-Performance EE CMOS In-System Programmable Logic
footprint fpBGA144 (BGA, 144-Leads, Body 13x13mm, Pitch 1mm)
3D model M4A3-fpBGA144 (144-Ball Fine Pitch Ball Grid Array (fpBGA144))
pins: A1 GND (power), A2 I/O15 B7 (io), A3 I/O13 B5 (io), A4 I/O8 B0 (io), A5 I/O6 A6 (io), A6 I/O2 A2 (io), A7 I0 (in), A8 GBCLK3 (in), A9 I13 (in), A10 I/O91 L3 (io), A11 I/O95 L7 (io), A12 GND (power), B1 TDI (in), B2 I/O31 D7 (io), B3 I/O14 B6 (io), B4 I/O10 B2 (io), B5 I/O7 A7 (io), B6 I/O3 A3 (io), B7 I1 (in), B8 VCC (power), B9 I/O88 L0 (io), B10 I/O90 L2 (io), B11 I/O94 L6 (io), B12 GND (power), C1 I/O28 D4 (io), C2 I/O27 D3 (io), C3 I/O30 D6 (io), C4 I/O12 B4 (io), C5 GND (power), C6 I/O4 A4 (io), C7 I/O0 A0 (io), C8 GND (power), C9 I14 (in), C10 I/O93 L5 (io), C11 TDO (out), C12 GND (power), D1 I/O24 D0 (io), D2 I/O25 D1 (io), D3 I2 (in), D4 I/O29 D5 (io), D5 I/O11 B3 (io), D6 VCC (power), D7 I/O1 A1 (io), D8 GBCLK0 (in), D9 I/O92 L4 (io), D10 I/O80 K0 (io), D11 I/O82 K2 (io), D12 I/O84 K4 (io), E1 VCC (power), E2 GND (power), E3 I4 (in), E4 I/O23 C7 (io), E5 I/O26 D2 (io), E6 I/O9 B1 (io), E7 I/O5 A5 (io), E8 I/O89 L1 (io), E9 I/O81 K1 (io), E10 I/O85 K5 (io), E11 I/O87 K7 (io), E12 I12 (in), F1 I/O22 C6 (io), F2 I/O21 C5 (io), F3 I/O20 C4 (io), F4 I/O19 C3 (io), F5 GND (power), F6 I3 (in), F7 I15 (in), F8 I/O83 K3 (io), F9 I/O86 K6 (io), F10 GND (power), F11 I11 (in), F12 I10 (in), G1 I/O18 C2 (io), G2 I/O17 C1 (io), G3 I/O16 C0 (io), G4 I/O38 E6 (io), G5 I/O35 E3 (io), G6 I7 (in), G7 GND (power), G8 VCC (power), G9 I/O72 J0 (io), G10 I/O73 J1 (io), G11 I/O74 J2 (io), G12 I/O75 J3 (io), H1 VCC (power), H2 I/O39 E7 (io), H3 I/O37 E5 (io), H4 I/O33 E1 (io), H5 I/O41 F1 (io), H6 I/O53 G5 (io), H7 I/O57 H1 (io), H8 I/O66 I2 (io), H9 I/O76 J4 (io), H10 I/O77 J5 (io), H11 I/O78 J6 (io), H12 I/O79 J7 (io), J1 I/O36 E4 (io), J2 I/O34 E2 (io), J3 I/O32 E0 (io), J4 I/O44 F4 (io), J5 GBCLK2 (in), J6 I/O49 G1 (io), J7 VCC (power), J8 I/O59 H3 (io), J9 I/O69 I5 (io), J10 VCC (power), J11 I/O65 I1 (io), J12 I/O64 I0 (io), K1 TMS (in), K2 TCK (in), K3 I/O45 F5 (io), K4 I6 (in), K5 VCC (power), K6 I/O48 G0 (io), K7 I/O52 G4 (io), K8 GND (power), K9 I/O60 H4 (io), K10 I/O70 I6 (io), K11 I/O67 I3 (io), K12 I/O68 I4 (io), L1 GND (power), L2 I/O46 F6 (io), L3 I/O42 F2 (io), L4 I/O40 F0 (io), L5 GND (power), L6 I9 (in), L7 I/O51 G3 (io), L8 I/O55 G7 (io), L9 I/O58 H2 (io), L10 I/O62 H6 (io), L11 I/O71 I7 (io), L12 GND (power), M1 GND (power), M2 I/O47 F7 (io), M3 I/O43 F3 (io), M4 I5 (in), M5 GBCLK1 (in), M6 I8 (in), M7 I/O50 G2 (io), M8 I/O54 G6 (io), M9 I/O56 H0 (io), M10 I/O61 H5 (io), M11 I/O63 H7 (io), M12 GND (power)

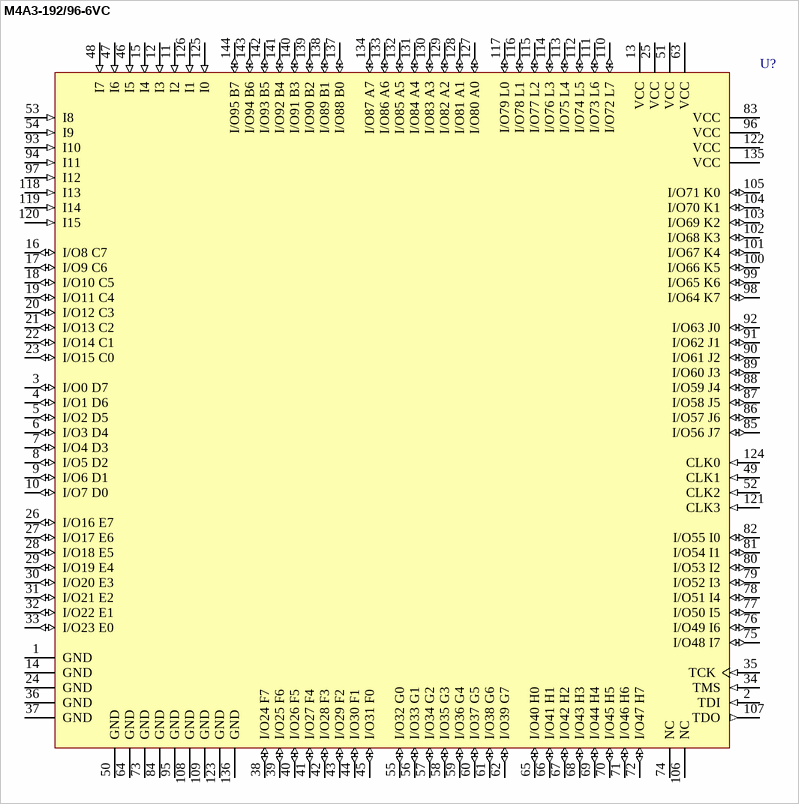
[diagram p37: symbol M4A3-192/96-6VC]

## M4A3-192/96-6VC
designator U?
High-Performance EE CMOS In-System Programmable Logic
footprint TQFP144_N (Thin QFP, 144-Leads, Body 20x20mm, Pitch 0.5mm, IPC Medium Density)
footprint TQFP144_L (Thin QFP, 144-Leads, Body 20x20mm, Pitch 0.5mm, IPC High Density)
footprint TQFP144_M (Thin QFP, 144-Leads, Body 20x20mm, Pitch 0.5mm, IPC Low Density)
3D model M4A3-TQFP144 (144-Pin Thin Quad Flat Pack (TQFP144))
pins: 1 GND (power), 2 TDI (in), 3 I/O0 D7 (io), 4 I/O1 D6 (io), 5 I/O2 D5 (io), 6 I/O3 D4 (io), 7 I/O4 D3 (io), 8 I/O5 D2 (io), 9 I/O6 D1 (io), 10 I/O7 D0 (io), 11 I2 (in), 12 I3 (in), 13 VCC (power), 14 GND (power), 15 I4 (in), 16 I/O8 C7 (io), 17 I/O9 C6 (io), 18 I/O10 C5 (io), 19 I/O11 C4 (io), 20 I/O12 C3 (io), 21 I/O13 C2 (io), 22 I/O14 C1 (io), 23 I/O15 C0 (io), 24 GND (power), 25 VCC (power), 26 I/O16 E7 (io), 27 I/O17 E6 (io), 28 I/O18 E5 (io), 29 I/O19 E4 (io), 30 I/O20 E3 (io), 31 I/O21 E2 (io), 32 I/O22 E1 (io), 33 I/O23 E0 (io), 34 TMS (in), 35 TCK (in), 36 GND (power), 37 GND (power), 38 I/O24 F7 (io), 39 I/O25 F6 (io), 40 I/O26 F5 (io), 41 I/O27 F4 (io), 42 I/O28 F3 (io), 43 I/O29 F2 (io), 44 I/O30 F1 (io), 45 I/O31 F0 (io), 46 I5 (in), 47 I6 (in), 48 I7 (in), 49 CLK1 (in), 50 GND (power), 51 VCC (power), 52 CLK2 (in), 53 I8 (in), 54 I9 (in), 55 I/O32 G0 (io), 56 I/O33 G1 (io), 57 I/O34 G2 (io), 58 I/O35 G3 (io), 59 I/O36 G4 (io), 60 I/O37 G5 (io), 61 I/O38 G6 (io), 62 I/O39 G7 (io), 63 VCC (power), 64 GND (power), 65 I/O40 H0 (io), 66 I/O41 H1 (io), 67 I/O42 H2 (io), 68 I/O43 H3 (io), 69 I/O44 H4 (io), 70 I/O45 H5 (io), 71 I/O46 H6 (io), 72 I/O47 H7 (io), 73 GND (power), 74 NC, 75 I/O48 I7 (io), 76 I/O49 I6 (io), 77 I/O50 I5 (io), 78 I/O51 I4 (io), 79 I/O52 I3 (io), 80 I/O53 I2 (io), 81 I/O54 I1 (io), 82 I/O55 I0 (io), 83 VCC (power), 84 GND (power), 85 I/O56 J7 (io), 86 I/O57 J6 (io), 87 I/O58 J5 (io), 88 I/O59 J4 (io), 89 I/O60 J3 (io), 90 I/O61 J2 (io), 91 I/O62 J1 (io), 92 I/O63 J0 (io), 93 I10 (in), 94 I11 (in), 95 GND (power), 96 VCC (power), 97 I12 (in), 98 I/O64 K7 (io), 99 I/O65 K6 (io), 100 I/O66 K5 (io), 101 I/O67 K4 (io), 102 I/O68 K3 (io), 103 I/O69 K2 (io), 104 I/O70 K1 (io), 105 I/O71 K0 (io), 106 NC, 107 TDO (out), 108 GND (power), 109 GND (power), 110 I/O72 L7 (io), 111 I/O73 L6 (io), 112 I/O74 L5 (io), 113 I/O75 L4 (io), 114 I/O76 L3 (io), 115 I/O77 L2 (io), 116 I/O78 L1 (io), 117 I/O79 L0 (io), 118 I13 (in), 119 I14 (in), 120 I15 (in), 121 CLK3 (in), 122 VCC (power), 123 GND (power), 124 CLK0 (in), 125 I0 (in), 126 I1 (in), 127 I/O80 A0 (io), 128 I/O81 A1 (io), 129 I/O82 A2 (io), 130 I/O83 A3 (io), 131 I/O84 A4 (io), 132 I/O85 A5 (io), 133 I/O86 A6 (io), 134 I/O87 A7 (io), 135 VCC (power), 136 GND (power), 137 I/O88 B0 (io), 138 I/O89 B1 (io), 139 I/O90 B2 (io), 140 I/O91 B3 (io), 141 I/O92 B4 (io), 142 I/O93 B5 (io), 143 I/O94 B6 (io), 144 I/O95 B7 (io)

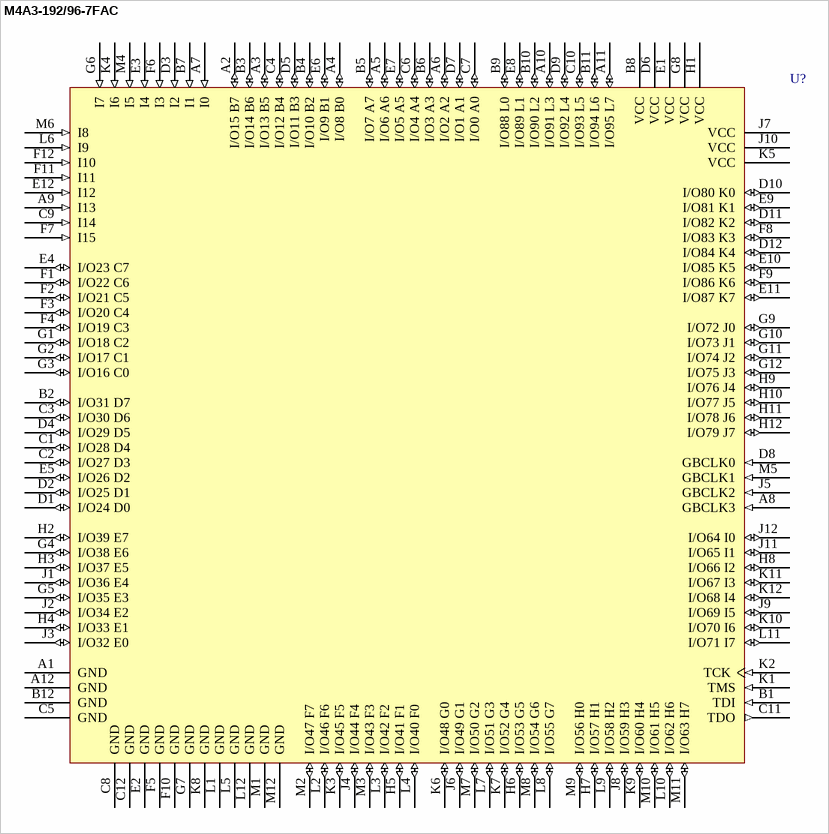
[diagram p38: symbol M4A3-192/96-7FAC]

## M4A3-192/96-7FAC
designator U?
High-Performance EE CMOS In-System Programmable Logic
footprint fpBGA144 (BGA, 144-Leads, Body 13x13mm, Pitch 1mm)
3D model M4A3-fpBGA144 (144-Ball Fine Pitch Ball Grid Array (fpBGA144))
pins: A1 GND (power), A2 I/O15 B7 (io), A3 I/O13 B5 (io), A4 I/O8 B0 (io), A5 I/O6 A6 (io), A6 I/O2 A2 (io), A7 I0 (in), A8 GBCLK3 (in), A9 I13 (in), A10 I/O91 L3 (io), A11 I/O95 L7 (io), A12 GND (power), B1 TDI (in), B2 I/O31 D7 (io), B3 I/O14 B6 (io), B4 I/O10 B2 (io), B5 I/O7 A7 (io), B6 I/O3 A3 (io), B7 I1 (in), B8 VCC (power), B9 I/O88 L0 (io), B10 I/O90 L2 (io), B11 I/O94 L6 (io), B12 GND (power), C1 I/O28 D4 (io), C2 I/O27 D3 (io), C3 I/O30 D6 (io), C4 I/O12 B4 (io), C5 GND (power), C6 I/O4 A4 (io), C7 I/O0 A0 (io), C8 GND (power), C9 I14 (in), C10 I/O93 L5 (io), C11 TDO (out), C12 GND (power), D1 I/O24 D0 (io), D2 I/O25 D1 (io), D3 I2 (in), D4 I/O29 D5 (io), D5 I/O11 B3 (io), D6 VCC (power), D7 I/O1 A1 (io), D8 GBCLK0 (in), D9 I/O92 L4 (io), D10 I/O80 K0 (io), D11 I/O82 K2 (io), D12 I/O84 K4 (io), E1 VCC (power), E2 GND (power), E3 I4 (in), E4 I/O23 C7 (io), E5 I/O26 D2 (io), E6 I/O9 B1 (io), E7 I/O5 A5 (io), E8 I/O89 L1 (io), E9 I/O81 K1 (io), E10 I/O85 K5 (io), E11 I/O87 K7 (io), E12 I12 (in), F1 I/O22 C6 (io), F2 I/O21 C5 (io), F3 I/O20 C4 (io), F4 I/O19 C3 (io), F5 GND (power), F6 I3 (in), F7 I15 (in), F8 I/O83 K3 (io), F9 I/O86 K6 (io), F10 GND (power), F11 I11 (in), F12 I10 (in), G1 I/O18 C2 (io), G2 I/O17 C1 (io), G3 I/O16 C0 (io), G4 I/O38 E6 (io), G5 I/O35 E3 (io), G6 I7 (in), G7 GND (power), G8 VCC (power), G9 I/O72 J0 (io), G10 I/O73 J1 (io), G11 I/O74 J2 (io), G12 I/O75 J3 (io), H1 VCC (power), H2 I/O39 E7 (io), H3 I/O37 E5 (io), H4 I/O33 E1 (io), H5 I/O41 F1 (io), H6 I/O53 G5 (io), H7 I/O57 H1 (io), H8 I/O66 I2 (io), H9 I/O76 J4 (io), H10 I/O77 J5 (io), H11 I/O78 J6 (io), H12 I/O79 J7 (io), J1 I/O36 E4 (io), J2 I/O34 E2 (io), J3 I/O32 E0 (io), J4 I/O44 F4 (io), J5 GBCLK2 (in), J6 I/O49 G1 (io), J7 VCC (power), J8 I/O59 H3 (io), J9 I/O69 I5 (io), J10 VCC (power), J11 I/O65 I1 (io), J12 I/O64 I0 (io), K1 TMS (in), K2 TCK (in), K3 I/O45 F5 (io), K4 I6 (in), K5 VCC (power), K6 I/O48 G0 (io), K7 I/O52 G4 (io), K8 GND (power), K9 I/O60 H4 (io), K10 I/O70 I6 (io), K11 I/O67 I3 (io), K12 I/O68 I4 (io), L1 GND (power), L2 I/O46 F6 (io), L3 I/O42 F2 (io), L4 I/O40 F0 (io), L5 GND (power), L6 I9 (in), L7 I/O51 G3 (io), L8 I/O55 G7 (io), L9 I/O58 H2 (io), L10 I/O62 H6 (io), L11 I/O71 I7 (io), L12 GND (power), M1 GND (power), M2 I/O47 F7 (io), M3 I/O43 F3 (io), M4 I5 (in), M5 GBCLK1 (in), M6 I8 (in), M7 I/O50 G2 (io), M8 I/O54 G6 (io), M9 I/O56 H0 (io), M10 I/O61 H5 (io), M11 I/O63 H7 (io), M12 GND (power)

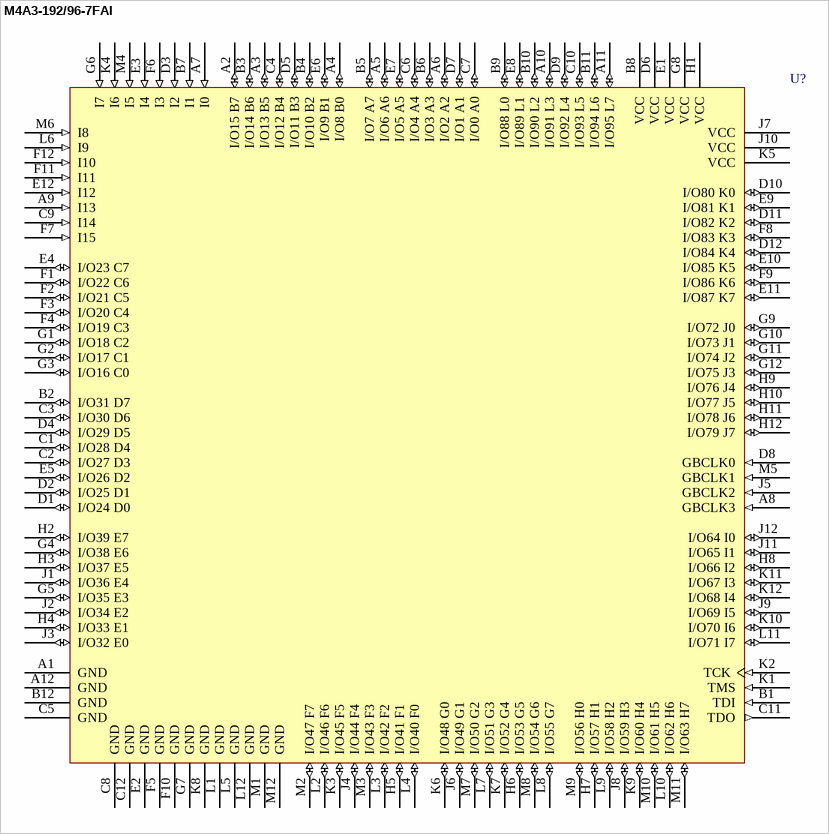
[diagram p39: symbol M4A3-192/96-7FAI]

## M4A3-192/96-7FAI
designator U?
High-Performance EE CMOS In-System Programmable Logic
footprint fpBGA144 (BGA, 144-Leads, Body 13x13mm, Pitch 1mm)
3D model M4A3-fpBGA144 (144-Ball Fine Pitch Ball Grid Array (fpBGA144))
pins: A1 GND (power), A2 I/O15 B7 (io), A3 I/O13 B5 (io), A4 I/O8 B0 (io), A5 I/O6 A6 (io), A6 I/O2 A2 (io), A7 I0 (in), A8 GBCLK3 (in), A9 I13 (in), A10 I/O91 L3 (io), A11 I/O95 L7 (io), A12 GND (power), B1 TDI (in), B2 I/O31 D7 (io), B3 I/O14 B6 (io), B4 I/O10 B2 (io), B5 I/O7 A7 (io), B6 I/O3 A3 (io), B7 I1 (in), B8 VCC (power), B9 I/O88 L0 (io), B10 I/O90 L2 (io), B11 I/O94 L6 (io), B12 GND (power), C1 I/O28 D4 (io), C2 I/O27 D3 (io), C3 I/O30 D6 (io), C4 I/O12 B4 (io), C5 GND (power), C6 I/O4 A4 (io), C7 I/O0 A0 (io), C8 GND (power), C9 I14 (in), C10 I/O93 L5 (io), C11 TDO (out), C12 GND (power), D1 I/O24 D0 (io), D2 I/O25 D1 (io), D3 I2 (in), D4 I/O29 D5 (io), D5 I/O11 B3 (io), D6 VCC (power), D7 I/O1 A1 (io), D8 GBCLK0 (in), D9 I/O92 L4 (io), D10 I/O80 K0 (io), D11 I/O82 K2 (io), D12 I/O84 K4 (io), E1 VCC (power), E2 GND (power), E3 I4 (in), E4 I/O23 C7 (io), E5 I/O26 D2 (io), E6 I/O9 B1 (io), E7 I/O5 A5 (io), E8 I/O89 L1 (io), E9 I/O81 K1 (io), E10 I/O85 K5 (io), E11 I/O87 K7 (io), E12 I12 (in), F1 I/O22 C6 (io), F2 I/O21 C5 (io), F3 I/O20 C4 (io), F4 I/O19 C3 (io), F5 GND (power), F6 I3 (in), F7 I15 (in), F8 I/O83 K3 (io), F9 I/O86 K6 (io), F10 GND (power), F11 I11 (in), F12 I10 (in), G1 I/O18 C2 (io), G2 I/O17 C1 (io), G3 I/O16 C0 (io), G4 I/O38 E6 (io), G5 I/O35 E3 (io), G6 I7 (in), G7 GND (power), G8 VCC (power), G9 I/O72 J0 (io), G10 I/O73 J1 (io), G11 I/O74 J2 (io), G12 I/O75 J3 (io), H1 VCC (power), H2 I/O39 E7 (io), H3 I/O37 E5 (io), H4 I/O33 E1 (io), H5 I/O41 F1 (io), H6 I/O53 G5 (io), H7 I/O57 H1 (io), H8 I/O66 I2 (io), H9 I/O76 J4 (io), H10 I/O77 J5 (io), H11 I/O78 J6 (io), H12 I/O79 J7 (io), J1 I/O36 E4 (io), J2 I/O34 E2 (io), J3 I/O32 E0 (io), J4 I/O44 F4 (io), J5 GBCLK2 (in), J6 I/O49 G1 (io), J7 VCC (power), J8 I/O59 H3 (io), J9 I/O69 I5 (io), J10 VCC (power), J11 I/O65 I1 (io), J12 I/O64 I0 (io), K1 TMS (in), K2 TCK (in), K3 I/O45 F5 (io), K4 I6 (in), K5 VCC (power), K6 I/O48 G0 (io), K7 I/O52 G4 (io), K8 GND (power), K9 I/O60 H4 (io), K10 I/O70 I6 (io), K11 I/O67 I3 (io), K12 I/O68 I4 (io), L1 GND (power), L2 I/O46 F6 (io), L3 I/O42 F2 (io), L4 I/O40 F0 (io), L5 GND (power), L6 I9 (in), L7 I/O51 G3 (io), L8 I/O55 G7 (io), L9 I/O58 H2 (io), L10 I/O62 H6 (io), L11 I/O71 I7 (io), L12 GND (power), M1 GND (power), M2 I/O47 F7 (io), M3 I/O43 F3 (io), M4 I5 (in), M5 GBCLK1 (in), M6 I8 (in), M7 I/O50 G2 (io), M8 I/O54 G6 (io), M9 I/O56 H0 (io), M10 I/O61 H5 (io), M11 I/O63 H7 (io), M12 GND (power)

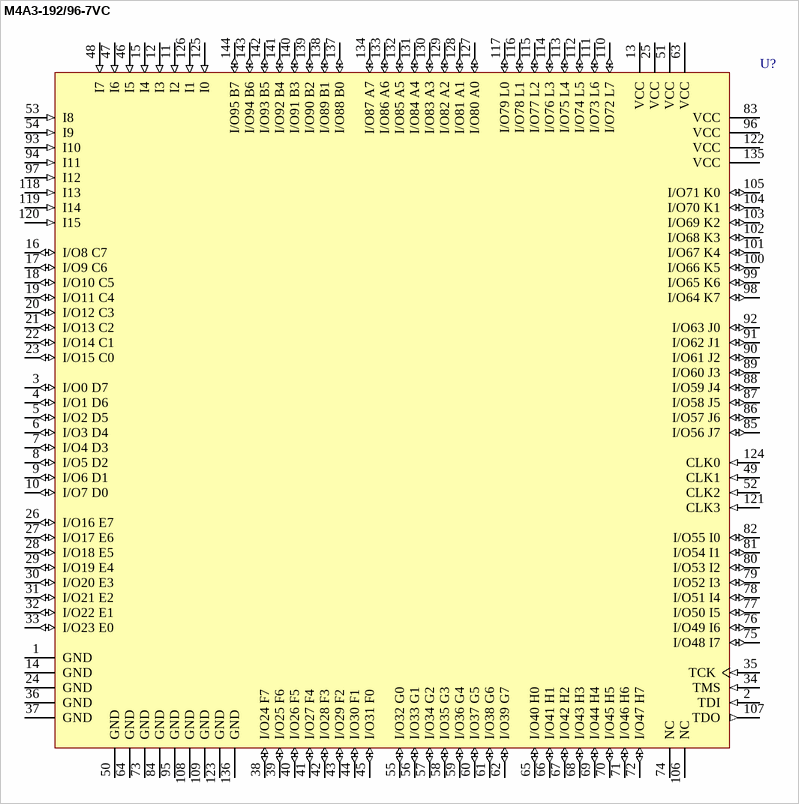
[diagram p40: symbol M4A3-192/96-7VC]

## M4A3-192/96-7VC
designator U?
High-Performance EE CMOS In-System Programmable Logic
footprint TQFP144_N (Thin QFP, 144-Leads, Body 20x20mm, Pitch 0.5mm, IPC Medium Density)
footprint TQFP144_L (Thin QFP, 144-Leads, Body 20x20mm, Pitch 0.5mm, IPC High Density)
footprint TQFP144_M (Thin QFP, 144-Leads, Body 20x20mm, Pitch 0.5mm, IPC Low Density)
3D model M4A3-TQFP144 (144-Pin Thin Quad Flat Pack (TQFP144))
pins: 1 GND (power), 2 TDI (in), 3 I/O0 D7 (io), 4 I/O1 D6 (io), 5 I/O2 D5 (io), 6 I/O3 D4 (io), 7 I/O4 D3 (io), 8 I/O5 D2 (io), 9 I/O6 D1 (io), 10 I/O7 D0 (io), 11 I2 (in), 12 I3 (in), 13 VCC (power), 14 GND (power), 15 I4 (in), 16 I/O8 C7 (io), 17 I/O9 C6 (io), 18 I/O10 C5 (io), 19 I/O11 C4 (io), 20 I/O12 C3 (io), 21 I/O13 C2 (io), 22 I/O14 C1 (io), 23 I/O15 C0 (io), 24 GND (power), 25 VCC (power), 26 I/O16 E7 (io), 27 I/O17 E6 (io), 28 I/O18 E5 (io), 29 I/O19 E4 (io), 30 I/O20 E3 (io), 31 I/O21 E2 (io), 32 I/O22 E1 (io), 33 I/O23 E0 (io), 34 TMS (in), 35 TCK (in), 36 GND (power), 37 GND (power), 38 I/O24 F7 (io), 39 I/O25 F6 (io), 40 I/O26 F5 (io), 41 I/O27 F4 (io), 42 I/O28 F3 (io), 43 I/O29 F2 (io), 44 I/O30 F1 (io), 45 I/O31 F0 (io), 46 I5 (in), 47 I6 (in), 48 I7 (in), 49 CLK1 (in), 50 GND (power), 51 VCC (power), 52 CLK2 (in), 53 I8 (in), 54 I9 (in), 55 I/O32 G0 (io), 56 I/O33 G1 (io), 57 I/O34 G2 (io), 58 I/O35 G3 (io), 59 I/O36 G4 (io), 60 I/O37 G5 (io), 61 I/O38 G6 (io), 62 I/O39 G7 (io), 63 VCC (power), 64 GND (power), 65 I/O40 H0 (io), 66 I/O41 H1 (io), 67 I/O42 H2 (io), 68 I/O43 H3 (io), 69 I/O44 H4 (io), 70 I/O45 H5 (io), 71 I/O46 H6 (io), 72 I/O47 H7 (io), 73 GND (power), 74 NC, 75 I/O48 I7 (io), 76 I/O49 I6 (io), 77 I/O50 I5 (io), 78 I/O51 I4 (io), 79 I/O52 I3 (io), 80 I/O53 I2 (io), 81 I/O54 I1 (io), 82 I/O55 I0 (io), 83 VCC (power), 84 GND (power), 85 I/O56 J7 (io), 86 I/O57 J6 (io), 87 I/O58 J5 (io), 88 I/O59 J4 (io), 89 I/O60 J3 (io), 90 I/O61 J2 (io), 91 I/O62 J1 (io), 92 I/O63 J0 (io), 93 I10 (in), 94 I11 (in), 95 GND (power), 96 VCC (power), 97 I12 (in), 98 I/O64 K7 (io), 99 I/O65 K6 (io), 100 I/O66 K5 (io), 101 I/O67 K4 (io), 102 I/O68 K3 (io), 103 I/O69 K2 (io), 104 I/O70 K1 (io), 105 I/O71 K0 (io), 106 NC, 107 TDO (out), 108 GND (power), 109 GND (power), 110 I/O72 L7 (io), 111 I/O73 L6 (io), 112 I/O74 L5 (io), 113 I/O75 L4 (io), 114 I/O76 L3 (io), 115 I/O77 L2 (io), 116 I/O78 L1 (io), 117 I/O79 L0 (io), 118 I13 (in), 119 I14 (in), 120 I15 (in), 121 CLK3 (in), 122 VCC (power), 123 GND (power), 124 CLK0 (in), 125 I0 (in), 126 I1 (in), 127 I/O80 A0 (io), 128 I/O81 A1 (io), 129 I/O82 A2 (io), 130 I/O83 A3 (io), 131 I/O84 A4 (io), 132 I/O85 A5 (io), 133 I/O86 A6 (io), 134 I/O87 A7 (io), 135 VCC (power), 136 GND (power), 137 I/O88 B0 (io), 138 I/O89 B1 (io), 139 I/O90 B2 (io), 140 I/O91 B3 (io), 141 I/O92 B4 (io), 142 I/O93 B5 (io), 143 I/O94 B6 (io), 144 I/O95 B7 (io)

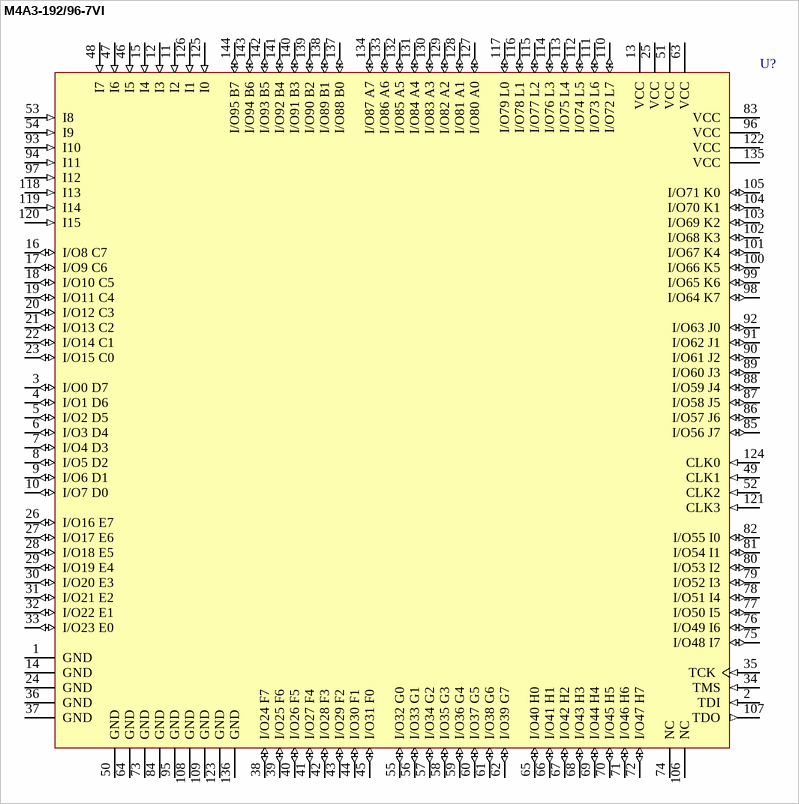
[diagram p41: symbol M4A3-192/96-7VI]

## M4A3-192/96-7VI
designator U?
High-Performance EE CMOS In-System Programmable Logic
footprint TQFP144_N (Thin QFP, 144-Leads, Body 20x20mm, Pitch 0.5mm, IPC Medium Density)
footprint TQFP144_L (Thin QFP, 144-Leads, Body 20x20mm, Pitch 0.5mm, IPC High Density)
footprint TQFP144_M (Thin QFP, 144-Leads, Body 20x20mm, Pitch 0.5mm, IPC Low Density)
3D model M4A3-TQFP144 (144-Pin Thin Quad Flat Pack (TQFP144))
pins: 1 GND (power), 2 TDI (in), 3 I/O0 D7 (io), 4 I/O1 D6 (io), 5 I/O2 D5 (io), 6 I/O3 D4 (io), 7 I/O4 D3 (io), 8 I/O5 D2 (io), 9 I/O6 D1 (io), 10 I/O7 D0 (io), 11 I2 (in), 12 I3 (in), 13 VCC (power), 14 GND (power), 15 I4 (in), 16 I/O8 C7 (io), 17 I/O9 C6 (io), 18 I/O10 C5 (io), 19 I/O11 C4 (io), 20 I/O12 C3 (io), 21 I/O13 C2 (io), 22 I/O14 C1 (io), 23 I/O15 C0 (io), 24 GND (power), 25 VCC (power), 26 I/O16 E7 (io), 27 I/O17 E6 (io), 28 I/O18 E5 (io), 29 I/O19 E4 (io), 30 I/O20 E3 (io), 31 I/O21 E2 (io), 32 I/O22 E1 (io), 33 I/O23 E0 (io), 34 TMS (in), 35 TCK (in), 36 GND (power), 37 GND (power), 38 I/O24 F7 (io), 39 I/O25 F6 (io), 40 I/O26 F5 (io), 41 I/O27 F4 (io), 42 I/O28 F3 (io), 43 I/O29 F2 (io), 44 I/O30 F1 (io), 45 I/O31 F0 (io), 46 I5 (in), 47 I6 (in), 48 I7 (in), 49 CLK1 (in), 50 GND (power), 51 VCC (power), 52 CLK2 (in), 53 I8 (in), 54 I9 (in), 55 I/O32 G0 (io), 56 I/O33 G1 (io), 57 I/O34 G2 (io), 58 I/O35 G3 (io), 59 I/O36 G4 (io), 60 I/O37 G5 (io), 61 I/O38 G6 (io), 62 I/O39 G7 (io), 63 VCC (power), 64 GND (power), 65 I/O40 H0 (io), 66 I/O41 H1 (io), 67 I/O42 H2 (io), 68 I/O43 H3 (io), 69 I/O44 H4 (io), 70 I/O45 H5 (io), 71 I/O46 H6 (io), 72 I/O47 H7 (io), 73 GND (power), 74 NC, 75 I/O48 I7 (io), 76 I/O49 I6 (io), 77 I/O50 I5 (io), 78 I/O51 I4 (io), 79 I/O52 I3 (io), 80 I/O53 I2 (io), 81 I/O54 I1 (io), 82 I/O55 I0 (io), 83 VCC (power), 84 GND (power), 85 I/O56 J7 (io), 86 I/O57 J6 (io), 87 I/O58 J5 (io), 88 I/O59 J4 (io), 89 I/O60 J3 (io), 90 I/O61 J2 (io), 91 I/O62 J1 (io), 92 I/O63 J0 (io), 93 I10 (in), 94 I11 (in), 95 GND (power), 96 VCC (power), 97 I12 (in), 98 I/O64 K7 (io), 99 I/O65 K6 (io), 100 I/O66 K5 (io), 101 I/O67 K4 (io), 102 I/O68 K3 (io), 103 I/O69 K2 (io), 104 I/O70 K1 (io), 105 I/O71 K0 (io), 106 NC, 107 TDO (out), 108 GND (power), 109 GND (power), 110 I/O72 L7 (io), 111 I/O73 L6 (io), 112 I/O74 L5 (io), 113 I/O75 L4 (io), 114 I/O76 L3 (io), 115 I/O77 L2 (io), 116 I/O78 L1 (io), 117 I/O79 L0 (io), 118 I13 (in), 119 I14 (in), 120 I15 (in), 121 CLK3 (in), 122 VCC (power), 123 GND (power), 124 CLK0 (in), 125 I0 (in), 126 I1 (in), 127 I/O80 A0 (io), 128 I/O81 A1 (io), 129 I/O82 A2 (io), 130 I/O83 A3 (io), 131 I/O84 A4 (io), 132 I/O85 A5 (io), 133 I/O86 A6 (io), 134 I/O87 A7 (io), 135 VCC (power), 136 GND (power), 137 I/O88 B0 (io), 138 I/O89 B1 (io), 139 I/O90 B2 (io), 140 I/O91 B3 (io), 141 I/O92 B4 (io), 142 I/O93 B5 (io), 143 I/O94 B6 (io), 144 I/O95 B7 (io)

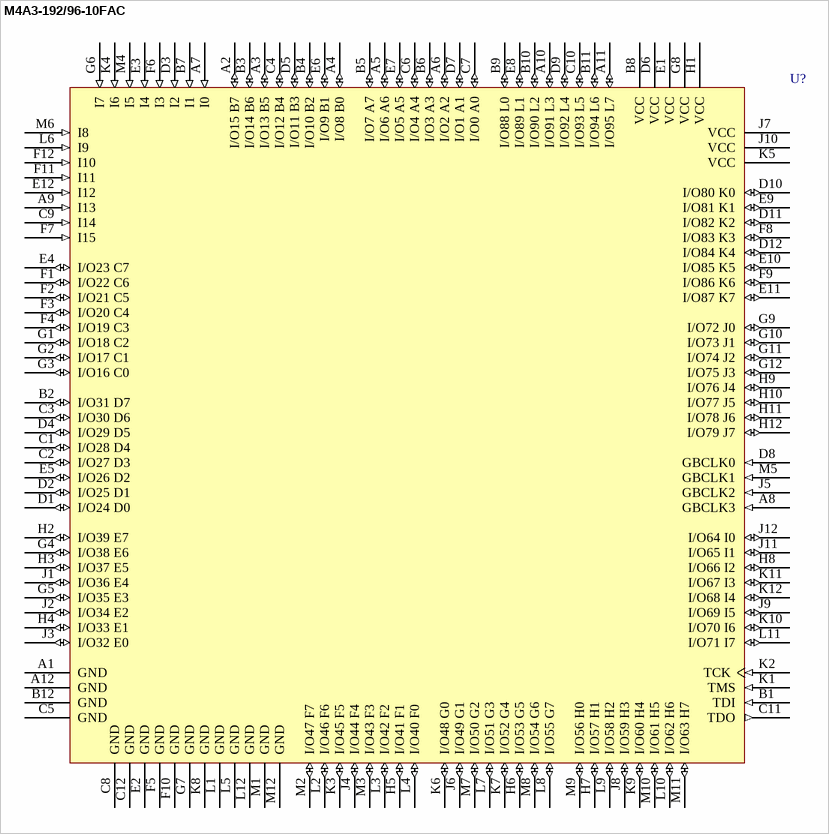
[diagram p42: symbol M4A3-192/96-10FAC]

## M4A3-192/96-10FAC
designator U?
High-Performance EE CMOS In-System Programmable Logic
footprint fpBGA144 (BGA, 144-Leads, Body 13x13mm, Pitch 1mm)
3D model M4A3-fpBGA144 (144-Ball Fine Pitch Ball Grid Array (fpBGA144))
pins: A1 GND (power), A2 I/O15 B7 (io), A3 I/O13 B5 (io), A4 I/O8 B0 (io), A5 I/O6 A6 (io), A6 I/O2 A2 (io), A7 I0 (in), A8 GBCLK3 (in), A9 I13 (in), A10 I/O91 L3 (io), A11 I/O95 L7 (io), A12 GND (power), B1 TDI (in), B2 I/O31 D7 (io), B3 I/O14 B6 (io), B4 I/O10 B2 (io), B5 I/O7 A7 (io), B6 I/O3 A3 (io), B7 I1 (in), B8 VCC (power), B9 I/O88 L0 (io), B10 I/O90 L2 (io), B11 I/O94 L6 (io), B12 GND (power), C1 I/O28 D4 (io), C2 I/O27 D3 (io), C3 I/O30 D6 (io), C4 I/O12 B4 (io), C5 GND (power), C6 I/O4 A4 (io), C7 I/O0 A0 (io), C8 GND (power), C9 I14 (in), C10 I/O93 L5 (io), C11 TDO (out), C12 GND (power), D1 I/O24 D0 (io), D2 I/O25 D1 (io), D3 I2 (in), D4 I/O29 D5 (io), D5 I/O11 B3 (io), D6 VCC (power), D7 I/O1 A1 (io), D8 GBCLK0 (in), D9 I/O92 L4 (io), D10 I/O80 K0 (io), D11 I/O82 K2 (io), D12 I/O84 K4 (io), E1 VCC (power), E2 GND (power), E3 I4 (in), E4 I/O23 C7 (io), E5 I/O26 D2 (io), E6 I/O9 B1 (io), E7 I/O5 A5 (io), E8 I/O89 L1 (io), E9 I/O81 K1 (io), E10 I/O85 K5 (io), E11 I/O87 K7 (io), E12 I12 (in), F1 I/O22 C6 (io), F2 I/O21 C5 (io), F3 I/O20 C4 (io), F4 I/O19 C3 (io), F5 GND (power), F6 I3 (in), F7 I15 (in), F8 I/O83 K3 (io), F9 I/O86 K6 (io), F10 GND (power), F11 I11 (in), F12 I10 (in), G1 I/O18 C2 (io), G2 I/O17 C1 (io), G3 I/O16 C0 (io), G4 I/O38 E6 (io), G5 I/O35 E3 (io), G6 I7 (in), G7 GND (power), G8 VCC (power), G9 I/O72 J0 (io), G10 I/O73 J1 (io), G11 I/O74 J2 (io), G12 I/O75 J3 (io), H1 VCC (power), H2 I/O39 E7 (io), H3 I/O37 E5 (io), H4 I/O33 E1 (io), H5 I/O41 F1 (io), H6 I/O53 G5 (io), H7 I/O57 H1 (io), H8 I/O66 I2 (io), H9 I/O76 J4 (io), H10 I/O77 J5 (io), H11 I/O78 J6 (io), H12 I/O79 J7 (io), J1 I/O36 E4 (io), J2 I/O34 E2 (io), J3 I/O32 E0 (io), J4 I/O44 F4 (io), J5 GBCLK2 (in), J6 I/O49 G1 (io), J7 VCC (power), J8 I/O59 H3 (io), J9 I/O69 I5 (io), J10 VCC (power), J11 I/O65 I1 (io), J12 I/O64 I0 (io), K1 TMS (in), K2 TCK (in), K3 I/O45 F5 (io), K4 I6 (in), K5 VCC (power), K6 I/O48 G0 (io), K7 I/O52 G4 (io), K8 GND (power), K9 I/O60 H4 (io), K10 I/O70 I6 (io), K11 I/O67 I3 (io), K12 I/O68 I4 (io), L1 GND (power), L2 I/O46 F6 (io), L3 I/O42 F2 (io), L4 I/O40 F0 (io), L5 GND (power), L6 I9 (in), L7 I/O51 G3 (io), L8 I/O55 G7 (io), L9 I/O58 H2 (io), L10 I/O62 H6 (io), L11 I/O71 I7 (io), L12 GND (power), M1 GND (power), M2 I/O47 F7 (io), M3 I/O43 F3 (io), M4 I5 (in), M5 GBCLK1 (in), M6 I8 (in), M7 I/O50 G2 (io), M8 I/O54 G6 (io), M9 I/O56 H0 (io), M10 I/O61 H5 (io), M11 I/O63 H7 (io), M12 GND (power)

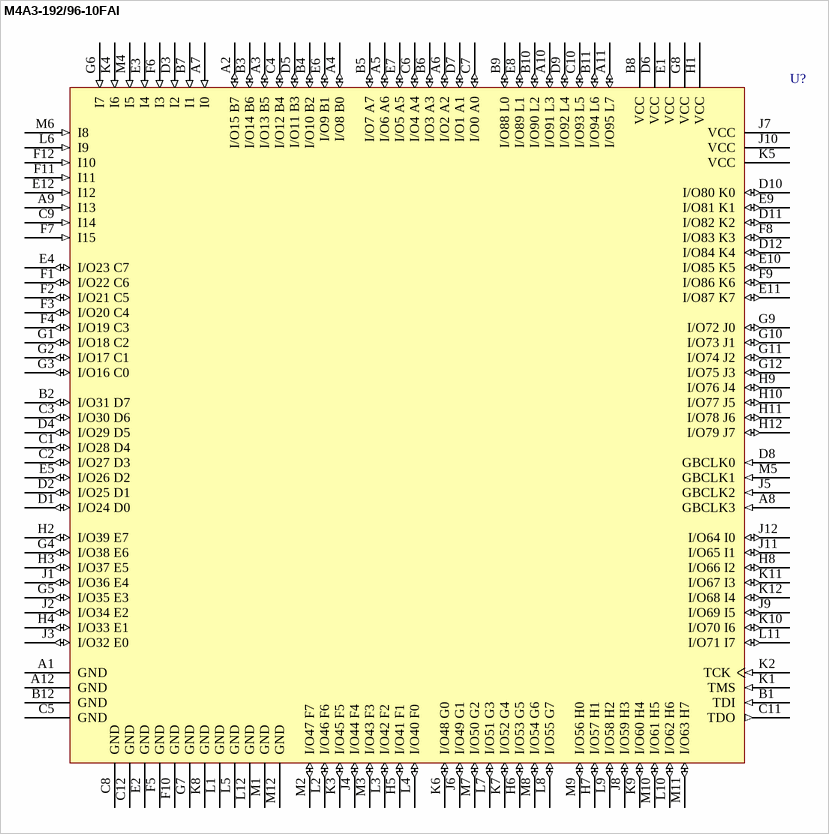
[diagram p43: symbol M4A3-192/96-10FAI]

## M4A3-192/96-10FAI
designator U?
High-Performance EE CMOS In-System Programmable Logic
footprint fpBGA144 (BGA, 144-Leads, Body 13x13mm, Pitch 1mm)
3D model M4A3-fpBGA144 (144-Ball Fine Pitch Ball Grid Array (fpBGA144))
pins: A1 GND (power), A2 I/O15 B7 (io), A3 I/O13 B5 (io), A4 I/O8 B0 (io), A5 I/O6 A6 (io), A6 I/O2 A2 (io), A7 I0 (in), A8 GBCLK3 (in), A9 I13 (in), A10 I/O91 L3 (io), A11 I/O95 L7 (io), A12 GND (power), B1 TDI (in), B2 I/O31 D7 (io), B3 I/O14 B6 (io), B4 I/O10 B2 (io), B5 I/O7 A7 (io), B6 I/O3 A3 (io), B7 I1 (in), B8 VCC (power), B9 I/O88 L0 (io), B10 I/O90 L2 (io), B11 I/O94 L6 (io), B12 GND (power), C1 I/O28 D4 (io), C2 I/O27 D3 (io), C3 I/O30 D6 (io), C4 I/O12 B4 (io), C5 GND (power), C6 I/O4 A4 (io), C7 I/O0 A0 (io), C8 GND (power), C9 I14 (in), C10 I/O93 L5 (io), C11 TDO (out), C12 GND (power), D1 I/O24 D0 (io), D2 I/O25 D1 (io), D3 I2 (in), D4 I/O29 D5 (io), D5 I/O11 B3 (io), D6 VCC (power), D7 I/O1 A1 (io), D8 GBCLK0 (in), D9 I/O92 L4 (io), D10 I/O80 K0 (io), D11 I/O82 K2 (io), D12 I/O84 K4 (io), E1 VCC (power), E2 GND (power), E3 I4 (in), E4 I/O23 C7 (io), E5 I/O26 D2 (io), E6 I/O9 B1 (io), E7 I/O5 A5 (io), E8 I/O89 L1 (io), E9 I/O81 K1 (io), E10 I/O85 K5 (io), E11 I/O87 K7 (io), E12 I12 (in), F1 I/O22 C6 (io), F2 I/O21 C5 (io), F3 I/O20 C4 (io), F4 I/O19 C3 (io), F5 GND (power), F6 I3 (in), F7 I15 (in), F8 I/O83 K3 (io), F9 I/O86 K6 (io), F10 GND (power), F11 I11 (in), F12 I10 (in), G1 I/O18 C2 (io), G2 I/O17 C1 (io), G3 I/O16 C0 (io), G4 I/O38 E6 (io), G5 I/O35 E3 (io), G6 I7 (in), G7 GND (power), G8 VCC (power), G9 I/O72 J0 (io), G10 I/O73 J1 (io), G11 I/O74 J2 (io), G12 I/O75 J3 (io), H1 VCC (power), H2 I/O39 E7 (io), H3 I/O37 E5 (io), H4 I/O33 E1 (io), H5 I/O41 F1 (io), H6 I/O53 G5 (io), H7 I/O57 H1 (io), H8 I/O66 I2 (io), H9 I/O76 J4 (io), H10 I/O77 J5 (io), H11 I/O78 J6 (io), H12 I/O79 J7 (io), J1 I/O36 E4 (io), J2 I/O34 E2 (io), J3 I/O32 E0 (io), J4 I/O44 F4 (io), J5 GBCLK2 (in), J6 I/O49 G1 (io), J7 VCC (power), J8 I/O59 H3 (io), J9 I/O69 I5 (io), J10 VCC (power), J11 I/O65 I1 (io), J12 I/O64 I0 (io), K1 TMS (in), K2 TCK (in), K3 I/O45 F5 (io), K4 I6 (in), K5 VCC (power), K6 I/O48 G0 (io), K7 I/O52 G4 (io), K8 GND (power), K9 I/O60 H4 (io), K10 I/O70 I6 (io), K11 I/O67 I3 (io), K12 I/O68 I4 (io), L1 GND (power), L2 I/O46 F6 (io), L3 I/O42 F2 (io), L4 I/O40 F0 (io), L5 GND (power), L6 I9 (in), L7 I/O51 G3 (io), L8 I/O55 G7 (io), L9 I/O58 H2 (io), L10 I/O62 H6 (io), L11 I/O71 I7 (io), L12 GND (power), M1 GND (power), M2 I/O47 F7 (io), M3 I/O43 F3 (io), M4 I5 (in), M5 GBCLK1 (in), M6 I8 (in), M7 I/O50 G2 (io), M8 I/O54 G6 (io), M9 I/O56 H0 (io), M10 I/O61 H5 (io), M11 I/O63 H7 (io), M12 GND (power)

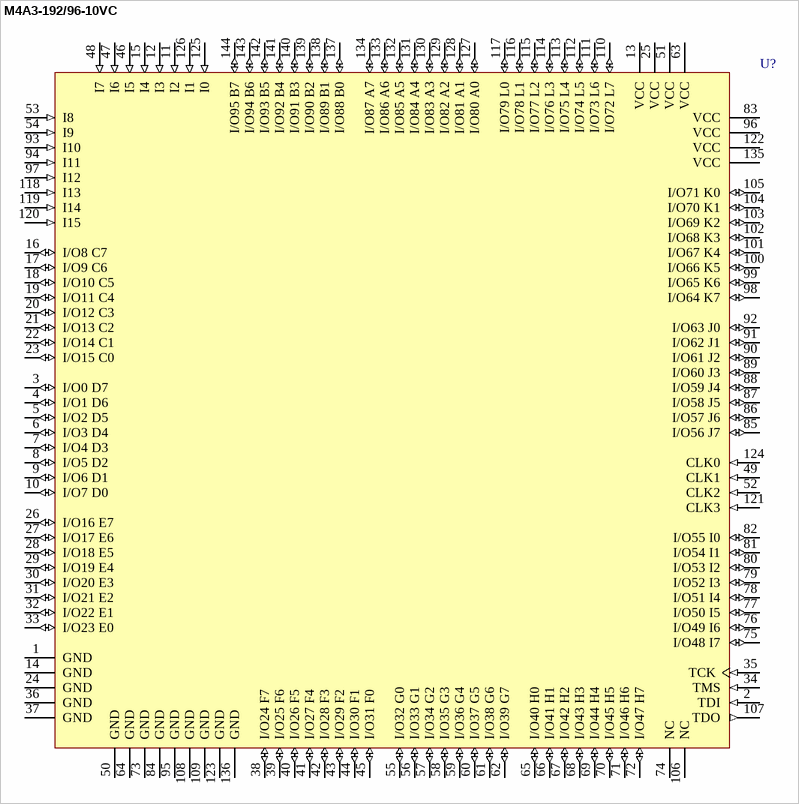
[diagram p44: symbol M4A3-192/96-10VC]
